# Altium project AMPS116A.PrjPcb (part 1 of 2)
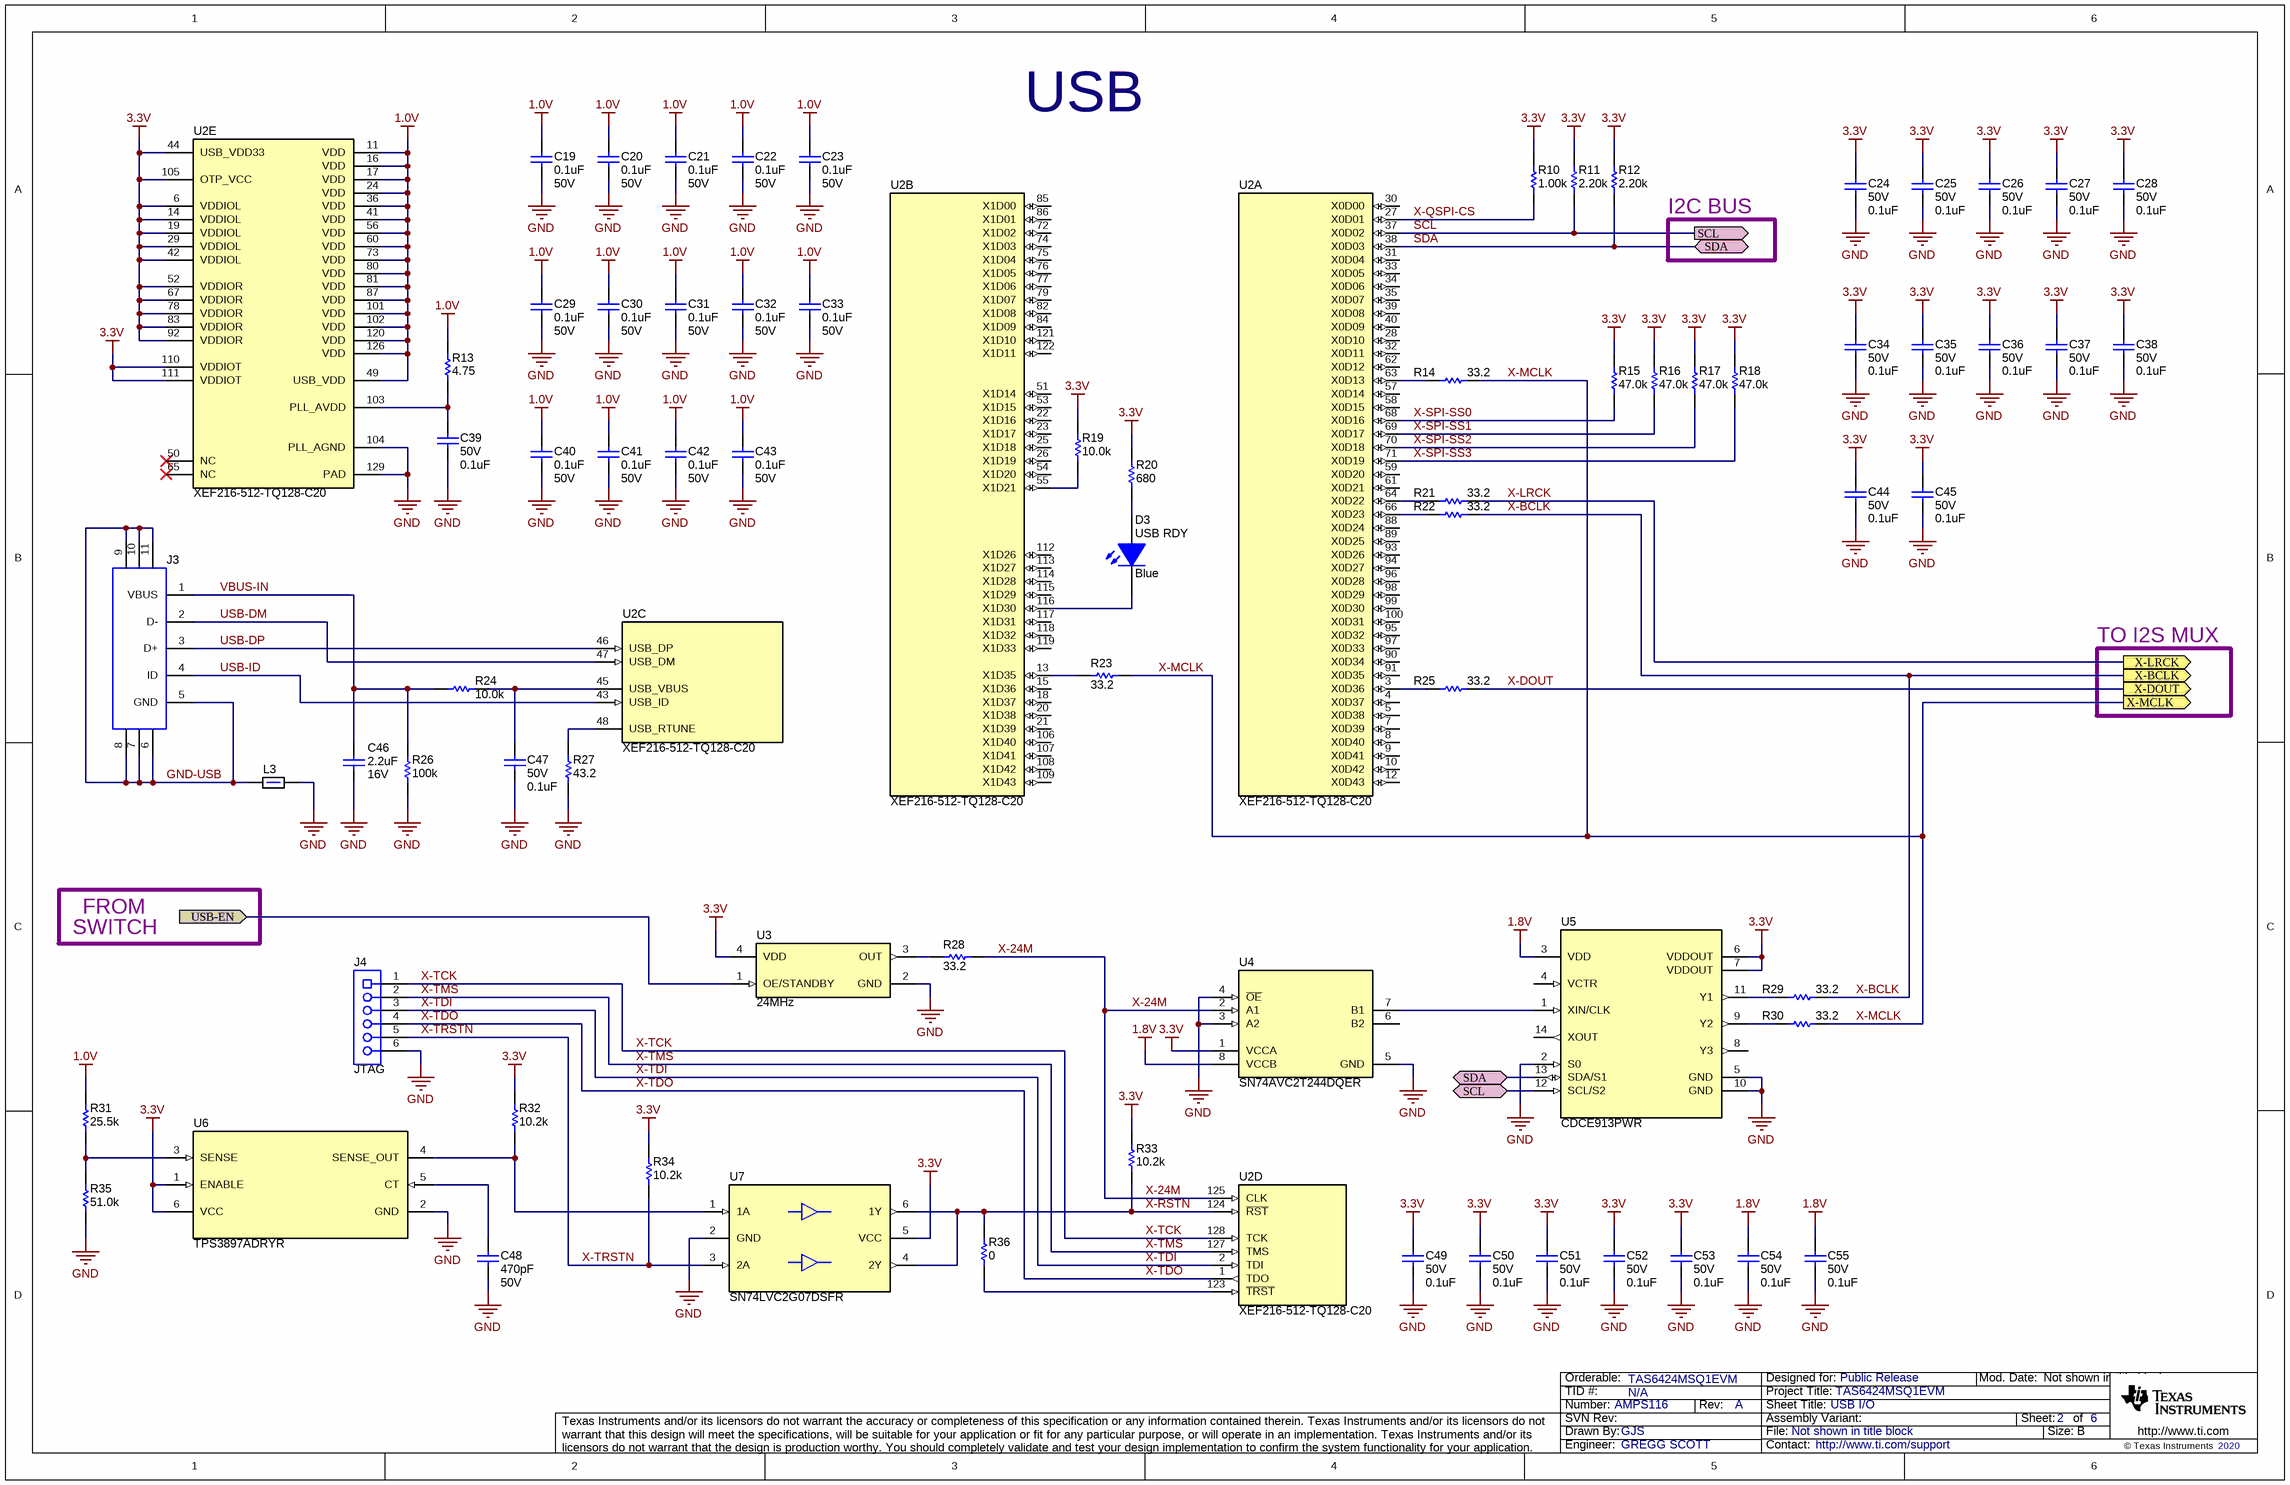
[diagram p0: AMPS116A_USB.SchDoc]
TID: N/A; TechSupport: http://www.ti.com/support; SCH_Rev: A; PRJ_Title: TAS6424MSQ1EVM; PRJ_Number: AMPS116; PRJ_Engineer: GREGG SCOTT; PRJ_Customer: Public Release; PCB_Rev: A; PCB_Layout: GJS; EVM_Orderable: TAS6424MSQ1EVM; CopyrightYear: 2020
5 sheets, 258 parts. Net scope: flat (ports and power ports of the same name join across sheets).
Board file: AMPS116A_EVM.PcbDoc
Sheets:
  AMPS116A_USB.SchDoc
  AMPS116A_SPDIF.SchDoc
  AMPS116A_TAS6424-IO.SchDoc
  AMPS116A_PowerSupplies.SchDoc
  AMPS116A_EVM_Hardware.SchDoc

## Sheet AMPS116A_USB.SchDoc: USB I/O
size 431 x 279 mm; Date: Not shown in title block; ApprovedBy: Not shown in title block; CheckedBy: Not shown in title block; Author: Not shown in title block; CompanyName: Not shown in title block; DrawnBy: GJS; Engineer: Not shown in title block; Organization: Not shown in title block; Address1: Not shown in title block; Address2: Not shown in title block; Address3: Not shown in title block; Address4: Not shown in title block; DocumentNumber: 2; Revision: Use project parameter SCH_Rev; SheetNumber: 2; SheetTotal: 6; PageSetup: Record=PageOptions¦CenterHorizontal=True¦CenterVertical=True¦PrintScale=0.77¦XCorrection=1.00¦YCorrection=1.00¦PrintKind=0¦BorderSize=5000000¦LeftOffset=0¦BottomOffset=0¦Orientation=2¦PaperLength=1000¦PaperWidth=1000¦Scale=100¦PaperSource=15¦PrintQuality=600¦MediaType=1¦DitherType=10¦PrintScaleMode=1¦PaperKind=Tabloid (11 x 17")¦PaperIndex=17

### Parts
C19  ValueDisplayed: 0.1uF  VDC_V: 50V  [0402L]  (hidden comment: Capacitor)
C20  ValueDisplayed: 0.1uF  VDC_V: 50V  [0402L]  (hidden comment: Capacitor)
C21  ValueDisplayed: 0.1uF  VDC_V: 50V  [0402L]  (hidden comment: Capacitor)
C22  ValueDisplayed: 0.1uF  VDC_V: 50V  [0402L]  (hidden comment: Capacitor)
C23  ValueDisplayed: 0.1uF  VDC_V: 50V  [0402L]  (hidden comment: Capacitor)
C24  VDC_V: 50V  ValueDisplayed: 0.1uF  [0402L]  (hidden comment: C1005X7R1H104K050BB)
C25  VDC_V: 50V  ValueDisplayed: 0.1uF  [0402L]  (hidden comment: C1005X7R1H104K050BB)
C26  VDC_V: 50V  ValueDisplayed: 0.1uF  [0402L]  (hidden comment: C1005X7R1H104K050BB)
C27  VDC_V: 50V  ValueDisplayed: 0.1uF  [0402L]  (hidden comment: C1005X7R1H104K050BB)
C28  VDC_V: 50V  ValueDisplayed: 0.1uF  [0402L]  (hidden comment: C1005X7R1H104K050BB)
C29  ValueDisplayed: 0.1uF  VDC_V: 50V  [0402L]  (hidden comment: Capacitor)
C30  ValueDisplayed: 0.1uF  VDC_V: 50V  [0402L]  (hidden comment: Capacitor)
C31  ValueDisplayed: 0.1uF  VDC_V: 50V  [0402L]  (hidden comment: Capacitor)
C32  ValueDisplayed: 0.1uF  VDC_V: 50V  [0402L]  (hidden comment: Capacitor)
C33  ValueDisplayed: 0.1uF  VDC_V: 50V  [0402L]  (hidden comment: Capacitor)
C34  VDC_V: 50V  ValueDisplayed: 0.1uF  [0402L]  (hidden comment: C1005X7R1H104K050BB)
C35  VDC_V: 50V  ValueDisplayed: 0.1uF  [0402L]  (hidden comment: C1005X7R1H104K050BB)
C36  VDC_V: 50V  ValueDisplayed: 0.1uF  [0402L]  (hidden comment: C1005X7R1H104K050BB)
C37  VDC_V: 50V  ValueDisplayed: 0.1uF  [0402L]  (hidden comment: C1005X7R1H104K050BB)
C38  VDC_V: 50V  ValueDisplayed: 0.1uF  [0402L]  (hidden comment: C1005X7R1H104K050BB)
C39  VDC_V: 50V  ValueDisplayed: 0.1uF  [0402L]  (hidden comment: C1005X7R1H104K050BB)
C40  ValueDisplayed: 0.1uF  VDC_V: 50V  [0402L]  (hidden comment: Capacitor)
C41  ValueDisplayed: 0.1uF  VDC_V: 50V  [0402L]  (hidden comment: Capacitor)
C42  ValueDisplayed: 0.1uF  VDC_V: 50V  [0402L]  (hidden comment: Capacitor)
C43  ValueDisplayed: 0.1uF  VDC_V: 50V  [0402L]  (hidden comment: Capacitor)
C44  VDC_V: 50V  ValueDisplayed: 0.1uF  [0402L]  (hidden comment: C1005X7R1H104K050BB)
C45  VDC_V: 50V  ValueDisplayed: 0.1uF  [0402L]  (hidden comment: C1005X7R1H104K050BB)
C46  VDC_V: 16V  ValueDisplayed: 2.2uF  [0603L]  (hidden comment: EMK107BB7225MA-T)
C47  VDC_V: 50V  ValueDisplayed: 0.1uF  [0402L]  (hidden comment: C1005X7R1H104K050BB)
C48  Cap_F: 470pF  VDC_V: 50V  [0402L]  (hidden comment: GRT1555C1H471JA02D)
C49  VDC_V: 50V  ValueDisplayed: 0.1uF  [0402L]  (hidden comment: C1005X7R1H104K050BB)
C50  VDC_V: 50V  ValueDisplayed: 0.1uF  [0402L]  (hidden comment: C1005X7R1H104K050BB)
C51  VDC_V: 50V  ValueDisplayed: 0.1uF  [0402L]  (hidden comment: C1005X7R1H104K050BB)
C52  VDC_V: 50V  ValueDisplayed: 0.1uF  [0402L]  (hidden comment: C1005X7R1H104K050BB)
C53  VDC_V: 50V  ValueDisplayed: 0.1uF  [0402L]  (hidden comment: C1005X7R1H104K050BB)
C54  VDC_V: 50V  ValueDisplayed: 0.1uF  [0402L]  (hidden comment: C1005X7R1H104K050BB)
C55  VDC_V: 50V  ValueDisplayed: 0.1uF  [0402L]  (hidden comment: C1005X7R1H104K050BB)
D3  USB RDY  value Blue  [LTST-C170TBKT_Blue]
J3  475890001  [Molex_0475890001]  (value not drawn)
J4  JTAG  [SULLINS_LPPB061NGCN-RC]
L3  MPZ2012S300AT000  [MPZ2012]  (value not drawn)
R10  ValueDisplayed: 1.00k  [0402L]  (hidden comment: ERJ-2RKF1001X)
R11  ValueDisplayed: 2.20k  [0402L]  (hidden comment: ERJ-2RKF2201X)
R12  ValueDisplayed: 2.20k  [0402L]  (hidden comment: ERJ-2RKF2201X)
R13  ValueDisplayed: 4.75  [0603L]  (hidden comment: RC0603FR-074R75L)
R14  ValueDisplayed: 33.2  [0201L]  (hidden comment: Resistor)
R15  ValueDisplayed: 47.0k  [0402L]  (hidden comment: RC0402FR-0747KL)
R16  ValueDisplayed: 47.0k  [0402L]  (hidden comment: RC0402FR-0747KL)
R17  ValueDisplayed: 47.0k  [0402L]  (hidden comment: RC0402FR-0747KL)
R18  ValueDisplayed: 47.0k  [0402L]  (hidden comment: RC0402FR-0747KL)
R19  ValueDisplayed: 10.0k  [0402L]  (hidden comment: RC0402FR-0710KL)
R20  ValueDisplayed: 680  [0603L]  (hidden comment: RC0603FR-07680RL)
R21  ValueDisplayed: 33.2  [0201L]  (hidden comment: Resistor)
R22  ValueDisplayed: 33.2  [0201L]  (hidden comment: Resistor)
R23  ValueDisplayed: 33.2  [0201L]  (hidden comment: Resistor)
R24  ValueDisplayed: 10.0k  [0402L]  (hidden comment: RC0402FR-0710KL)
R25  ValueDisplayed: 33.2  [0201L]  (hidden comment: Resistor)
R26  ValueDisplayed: 100k  [0402L]  (hidden comment: ERJ-2RKF1003X)
R27  ValueDisplayed: 43.2  [0603L]  (hidden comment: RC0603FR-0743R2L)
R28  ValueDisplayed: 33.2  [0201L]  (hidden comment: Resistor)
R29  ValueDisplayed: 33.2  [0201L]  (hidden comment: Resistor)
R30  ValueDisplayed: 33.2  [0201L]  (hidden comment: Resistor)
R31  ValueDisplayed: 25.5k  [0201L]  (hidden comment: Resistor)
R32  ValueDisplayed: 10.2k  [0201L]  (hidden comment: RC0201FR-0710K2L)
R33  ValueDisplayed: 10.2k  [0201L]  (hidden comment: RC0201FR-0710K2L)
R34  ValueDisplayed: 10.2k  [0201L]  (hidden comment: RC0201FR-0710K2L)
R35  ValueDisplayed: 51.0k  [0201L]  (hidden comment: Resistor)
R36  ValueDisplayed: 0  [0402L]  (hidden comment: ERJ-2GE0R00X)
U2  XEF216-512-TQ128-C20  [TQFP-128]  (parts A,B,C,D,E of 5)
U3  Frequency_Fixed: 24MHz  [Abracon_ASTMLPA]  (hidden comment: OSC_4P_1_OE-STBY)
U4  SN74AVC2T244DQER  [DQE0008A]
U5  CDCE913PWR  [PW0014A_L]
U6  TPS3897ADRYR  [DRY0006A]
U7  SN74LVC2G07DSFR  [DSF0006A]

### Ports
SCL (bidir), SCL (out), SDA (bidir), USB-EN (in), X-BCLK (out), X-DOUT (out), X-LRCK (out), X-MCLK (out)

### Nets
1.0V: C19.2 C20.2 C21.2 C22.2 C23.2 C29.2 C30.2 C31.2 C32.2 C33.2 C40.2 C41.2 C42.2 C43.2 R13.1 R31.1 U2.11(VDD) U2.16(VDD) U2.17(VDD) U2.24(VDD) U2.36(VDD) U2.41(VDD) U2.49(USB_VDD) U2.56(VDD) U2.60(VDD) U2.73(VDD) U2.80(VDD) U2.81(VDD) U2.87(VDD) U2.101(VDD) U2.102(VDD) U2.120(VDD) U2.126(VDD)
1.8V: C54.1 C55.1 U4.8(VCCB) U5.3(VDD)
3.3V: C24.1 C25.1 C26.1 C27.1 C28.1 C34.1 C35.1 C36.1 C37.1 C38.1 C44.1 C45.1 C49.1 C50.1 C51.1 C52.1 C53.1 R10.1 R11.1 R12.1 R15.2 R16.2 R17.2 R18.2 R19.2 R20.1 R32.1 R33.1 R34.1 U2.6(VDDIOL) U2.14(VDDIOL) U2.19(VDDIOL) U2.29(VDDIOL) U2.42(VDDIOL) U2.44(USB_VDD33) U2.52(VDDIOR) U2.67(VDDIOR) U2.78(VDDIOR) U2.83(VDDIOR) U2.92(VDDIOR) U2.105(OTP_VCC) U2.110(VDDIOT) U2.111(VDDIOT) U3.4(VDD) U4.1(VCCA) U5.6(VDDOUT) U5.7(VDDOUT) U6.1(ENABLE) U6.6(VCC) U7.5(VCC)
GND: C19.1 C20.1 C21.1 C22.1 C23.1 C24.2 C25.2 C26.2 C27.2 C28.2 C29.1 C30.1 C31.1 C32.1 C33.1 C34.2 C35.2 C36.2 C37.2 C38.2 C39.2 C40.1 C41.1 C42.1 C43.1 C44.2 C45.2 C46.2 C47.2 C48.2 C49.2 C50.2 C51.2 C52.2 C53.2 C54.2 C55.2 J4.6 L3.2 R26.1 R27.1 R35.2 U2.104(PLL_AGND) U2.129(PAD) U3.2(GND) U4.3(A2) U4.4(~{OE}) U4.5(GND) U5.2(S0) U5.5(GND) U5.10(GND) U6.2(GND) U7.2(GND)
GND-USB: J3.5(GND) J3.6 J3.7 J3.8 J3.9 J3.10 J3.11 L3.1
SCL: R11.2 U2.37(X0D02) U5.12(SCL/S2) ; port SCL
SDA: R12.2 U2.38(X0D03) U5.13(SDA/S1) ; port SDA
USB-DM: J3.2(D-) U2.47(USB_DM)
USB-DP: J3.3(D+) U2.46(USB_DP)
USB-EN: U3.1(OE/STANDBY) ; port USB-EN
USB-ID: J3.4(ID) U2.43(USB_ID)
VBUS-IN: C46.1 J3.1(VBUS) R24.2 R26.2
X-24M: R28.2 U2.125(CLK) U4.2(A1)
X-BCLK: R22.2 R29.2 ; port X-BCLK
X-DOUT: R25.2 ; port X-DOUT
X-LRCK: R21.2 ; port X-LRCK
X-MCLK: R14.2 R23.2 R30.2 ; port X-MCLK
X-QSPI-CS: R10.2 U2.27(X0D01)
X-RSTN: R33.2 R36.2 U2.124(~{RST}) U7.4(2Y) U7.6(1Y)
X-SPI-SS0: R15.1 U2.68(X0D16)
X-SPI-SS1: R16.1 U2.69(X0D17)
X-SPI-SS2: R17.1 U2.70(X0D18)
X-SPI-SS3: R18.1 U2.71(X0D19)
X-TCK: J4.1 U2.128(TCK)
X-TDI: J4.3 U2.2(TDI)
X-TDO: J4.4 U2.1(TDO)
X-TMS: J4.2 U2.127(TMS)
X-TRSTN: J4.5 R34.2 U7.3(2A)
NetC39_1: C39.1 R13.2 U2.103(PLL_AVDD)
NetC47_1: C47.1 R24.1 U2.45(USB_VBUS)
NetC48_1: C48.1 U6.5(CT)
NetD3_1: D3.1(A) R20.2
NetD3_2: D3.2(K) U2.116(X1D30)
NetR14_1: R14.1 U2.63(X0D13)
NetR19_1: R19.1 U2.55(X1D21)
NetR21_1: R21.1 U2.64(X0D22)
NetR22_1: R22.1 U2.66(X0D23)
NetR23_1: R23.1 U2.13(X1D35)
NetR25_1: R25.1 U2.3(X0D36)
NetR27_2: R27.2 U2.48(USB_RTUNE)
NetR28_1: R28.1 U3.3(OUT)
NetR29_1: R29.1 U5.11(Y1)
NetR30_1: R30.1 U5.9(Y2)
NetR31_2: R31.2 R35.1 U6.3(SENSE)
NetR32_2: R32.2 U6.4(SENSE_OUT) U7.1(1A)
NetR36_1: R36.1 U2.123(~{TRST})
NetU4_7: U4.7(B1) U5.1(XIN/CLK)

Not connected (* = marked no-connect by the designer): U2 4(X0D37) 5(X0D38) 7(X0D39) 8(X0D40) 9(X0D41) 10(X0D42) 12(X0D43) 15(X1D36) 18(X1D37) 20(X1D38) 21(X1D39) 22(X1D16) 23(X1D17) 25(X1D18) 26(X1D19) 28(X0D10) 30(X0D00) 31(X0D04) 32(X0D11) 33(X0D05) 34(X0D06) 35(X0D07) 39(X0D08) 40(X0D09) 50(NC)* 51(X1D14) 53(X1D15) 54(X1D20) 57(X0D14) 58(X0D15) 59(X0D20) 61(X0D21) 62(X0D12) 65(NC)* 72(X1D02) 74(X1D03) 75(X1D04) 76(X1D05) 77(X1D06) 79(X1D07) 82(X1D08) 84(X1D09) 85(X1D00) 86(X1D01) 88(X0D24) 89(X0D25) 90(X0D34) 91(X0D35) 93(X0D26) 94(X0D27) 95(X0D32) 96(X0D28) 97(X0D33) 98(X0D29) 99(X0D30) 100(X0D31) 106(X1D40) 107(X1D41) 108(X1D42) 109(X1D43) 112(X1D26) 113(X1D27) 114(X1D28) 115(X1D29) 117(X1D31) 118(X1D32) 119(X1D33) 121(X1D10) 122(X1D11); U4 6(B2); U5 4(VCTR) 8(Y3) 14(XOUT)

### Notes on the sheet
- USB
- I2C BUS
- TO I2S MUX
- SWITCH
- FROM

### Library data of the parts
C19-C23 C29-C33 C40-C43 = CMP-0006297-2: CAP, CERM, 0.1 uF, 50 V, +/- 10%, X7R, 0402; PartNumber: C1005X7R1H104K050BB; Manufacturer: TDK; Polarized: N; Value: 0.1uF; U/M: EA; Cap_F: 100nF; ESR_ohm: 0.039064; Value1: 0.039064 ohm; IRMS_A: 8.14669dA; TaMin_C: -55°C; TaMax_C: 125°C; Cap_Case: 0402; SizeArea_mm2: 0.5; SizeAreaWB_mm2: 3; SizeX_mm: 1; SizeZ_mm: 0.6; AEC Category: Q200
C24-C28 C34-C39 C44 C45 C47 C49-C55 = CMP-0006297-2: CAP, CERM, 0.1 uF, 50 V, +/- 10%, X7R, 0402; Manufacturer: TDK; TaMin_C: -55°C; Polarized: N; SizeAreaWB_mm2: 3; Value1: 0.039064 ohm; U/M: EA; Value: 0.1uF; TaMax_C: 125°C; SizeZ_mm: 0.6; SizeX_mm: 1; SizeY_mm: 0.5; Cap_Case: 0402; Cap_F: 100nF; AEC Category: Q200; ESR_ohm: 0.039064; IRMS_A: 8.14669dA
C46 = CMP-0064934-4: CAP, CERM, 2.2 uF, 16 V,+/- 10%, X7R, 0603; Manufacturer: Taiyo Yuden; TaMin_C: -55°C; Polarized: N; SizeAreaWB_mm2: 4.68; Value1: Unknown; U/M: EA; Value: 2.2uF; TaMax_C: 125°C; SizeZ_mm: 1; SizeX_mm: 1.6; SizeY_mm: 0.8; Cap_Case: 0603; SizeArea_mm2: 1.28; CompType: Capacitor; Cap_F: 2.2µF; AEC Category: Q200
C48 = CMP-0860800-1: CAP, CERM, 470 pF, 50 V,+/- 5%, C0G, AEC-Q200 Grade 1, 0402; Manufacturer: MuRata; U/M: EA; Polarized: N; AEC Category: Q200; SizeY_mm: 0.5; SizeAreaWB_mm2: 3; AEC Qualified: Y; TaMax_C: 125°C; Value: 470pF; SizeX_mm: 1; TaMin_C: -55°C; Cap_Case: 0402; SizeZ_mm: 0.6
D3 = CMP-0002889-2: LED, Blue, SMD; PartNumber: LTST-C170TBKT; Manufacturer: Lite-On; Type: AlInGaP; Value1: W; Io_A: 20mA; Vf_V: 3.3V
J3 = CMP-0055301-1: Connector, Receptacle, Micro-USB Type AB, R/A, Bottom Mount SMT; Manufacturer: Molex; CNHeader: FALSE; Green_Lifecycle: Active; Gender: Female; Green_REACh: Passed; CompType: USB; CT: TRUE
J4 = CMP-0054640-1: Receptacle, 50mil, 6x1, Gold, R/A, TH; PartNumber: LPPB061NGCN-RC; Manufacturer: Sullins Connector Solutions; CompType: Socket Strip; Pitch_mm: 1.27; Gender: Female; Row_Count: 1; CNHeader: FALSE; CT: TRUE; Green_Lifecycle: Active; Green_REACh: Passed
L3 = CMP-0003428-2: Ferrite Bead, 30 ohm @ 100 MHz, 6 A, 0805; Manufacturer: TDK; ZTyp@100MHz_Ohm: 30; SizeAreaWB_mm2: 6.75; DCR_ohm: 0.01; Value1: 0.01 ohm; Value: 30 ohm; Imax_A: 6A; SizeZ_mm: 1.45; SizeX_mm: 2; SizeY_mm: 1.25; SizeArea_mm2: 2.5
R10 = CMP-0026657-1: RES, 1.00 k, 1%, 0.1 W, 0402; Manufacturer: Panasonic; Power_W: 100mW; TempCo: 100 ppm/C; Value_Code: 1k00; U/M: EA; Value: 1.00k; EIA_Code: E96; Res_ohm: 1k; SizeX_mm: 1; SizeY_mm: 0.5; SizeZ_mm: 0.6; Value2: 0.1W; CompType: Resistor; VDC_V: 50V; AEC Category: Q200
R11 R12 = CMP-0026681-1: RES, 2.20 k, 1%, 0.1 W, 0402; Manufacturer: Panasonic; Value: 2.20k; Res_ohm: 2.2k; Value_Code: 2k20; Power_W: 100mW; Value2: 0.1W; VDC_V: 50V; TempCo: 100 ppm/C; AEC Category: Q200; SizeArea_mm2: 0.5; SizeX_mm: 1; SizeZ_mm: 0.6; U/M: EA
R13 = CMP-0023160-5: RES, 4.75, 1%, 0.1 W, 0603; Manufacturer: Yageo; Power_W: 100mW; TempCo: 200 ppm/C; Value_Code: 4R75; Value: 4.75; EIA_Code: E96; SizeX_mm: 1.6; SizeY_mm: 0.8; SizeZ_mm: 1; Value2: 0.1W; SizeArea_mm2: 1.28; CompType: Resistor; AEC Qualified: N; VDC_V: 75V; AEC Category: Q200; SizeAreaWB_mm2: 4.68
R14 R21-R23 R25 R29 R30 = CMP-0027614-1: RES, 33.2, 1%, 0.05 W, 0201; PartNumber: RC0201FR-0733R2L; Manufacturer: Yageo America; Value: 33.2; Value_Code: 33R2; Power_W: 50mW; Value2: 0.05W; VDC_V: 25V; TempCo: 200 ppm/C; SizeArea_mm2: 0.18; SizeX_mm: 0.6; SizeY_mm: 0.3; SizeZ_mm: 0.26; EIA_Code: E96; U/M: EA; AEC Category: Q200; AEC Qualified: N
R15-R18 = CMP-0026737-1: RES, 47.0 k, 1%, 0.0625 W, 0402; Manufacturer: Yageo America; Value: 47.0k; Res_ohm: 47k; Value_Code: 47k0; Power_W: 62.5mW; VDC_V: 50V; TempCo: 100 ppm/C; AEC Category: Q200; AEC Qualified: N; SizeArea_mm2: 0.5; SizeX_mm: 1; SizeZ_mm: 0.6; U/M: EA
R19 R24 = CMP-0078669-1: RES, 10.0 k, 1%, 0.063 W, 0402; Manufacturer: Yageo America; Power_W: 63mW; Green_Lifecycle: Active; TempCo: 100 ppm/C; Value_Code: 10k0; Green_REACh: Passed; Value: 10.0k; EIA_Code: E96; Res_ohm: 10k; SizeX_mm: 1; SizeY_mm: 0.5; SizeZ_mm: 0.6; Value2: 0.063W; CompType: Resistor; AEC Qualified: N; AEC Category: Q200
R20 = CMP-0023235-5: RES, 680, 1%, 0.1 W, 0603; Manufacturer: Yageo; Power_W: 100mW; TempCo: 100 ppm/C; Value_Code: 680R; Value: 680; SizeX_mm: 1.6; SizeY_mm: 0.8; SizeZ_mm: 1; Value2: 0.1W; SizeArea_mm2: 1.28; CompType: Resistor; AEC Qualified: N; VDC_V: 75V; AEC Category: Q200; SizeAreaWB_mm2: 4.68
R26 = CMP-0026659-2: RES, 100 k, 1%, 0.1 W, 0402; Manufacturer: Panasonic; Value: 100k; Power_W: 100mW; Value2: 0.1W; VDC_V: 50V; TempCo: 100 ppm/C; EIA_Code: E96; U/M: EA; AEC Category: Q200; AEC Qualified: Yes; AEC Grade: 0; SizeArea_mm2: 0.5; SizeX_mm: 1; SizeZ_mm: 0.6
R27 = CMP-0023114-5: RES, 43.2, 1%, 0.1 W, 0603; Manufacturer: Yageo; Power_W: 100mW; TempCo: 100 ppm/C; Value_Code: 43R2; Value: 43.2; EIA_Code: E96; SizeX_mm: 1.6; SizeY_mm: 0.8; SizeZ_mm: 1; Value2: 0.1W; SizeArea_mm2: 1.28; CompType: Resistor; AEC Qualified: N; VDC_V: 75V; AEC Category: Q200; SizeAreaWB_mm2: 4.68
R28 = CMP-0027614-1: RES, 33.2, 1%, 0.05 W, 0201; PartNumber: RC0201FR-0733R2L; Manufacturer: Yageo America; Value: 33.2; Value_Code: 33R2; Power_W: 50mW; Value2: 0.05W; VDC_V: 25V; TempCo: 200 ppm/C; EIA_Code: E96; U/M: EA; SizeArea_mm2: 0.18; SizeX_mm: 0.6; SizeY_mm: 0.3; SizeZ_mm: 0.26; AEC Category: Q200; AEC Qualified: N
R31 = CMP-0027523-1: RES, 25.5 k, 1%, 0.05 W, 0201; PartNumber: RC0201FR-0725K5L; Manufacturer: Yageo America; Value: 25.5k; Value_Code: 25k5; Power_W: 50mW; Value2: 0.05W; VDC_V: 25V; TempCo: 200 ppm/C; SizeArea_mm2: 0.18; SizeX_mm: 0.6; SizeY_mm: 0.3; SizeZ_mm: 0.26; EIA_Code: E96; U/M: EA; AEC Category: Q200; AEC Qualified: N
R32-R34 = CMP-0027301-2: RES, 10.2 k, 1%, 0.05 W, 0201; Manufacturer: Yageo America; Value: 10.2k; Value_Code: 10k2; Power_W: 50mW; Value2: 0.05W; VDC_V: 25V; TempCo: 200 ppm/C; SizeArea_mm2: 0.18; SizeX_mm: 0.6; SizeY_mm: 0.3; SizeZ_mm: 0.26; EIA_Code: E96; AEC Category: Q200; AEC Qualified: N; U/M: EA
R35 = CMP-0027757-1: RES, 51.0 k, 1%, 0.05 W, 0201; PartNumber: RC0201FR-0751KL; Manufacturer: Yageo America; Value: 51.0k; Res_ohm: 51k; Value_Code: 51k0; Power_W: 50mW; Value2: 0.05W; VDC_V: 25V; TempCo: 200 ppm/C; SizeArea_mm2: 0.18; SizeX_mm: 0.6; SizeY_mm: 0.3; SizeZ_mm: 0.26; U/M: EA; AEC Category: Q200; AEC Qualified: N
R36 = CMP-0026992-3: RES, 0, 5%, 0.1 W, AEC-Q200 Grade 0, 0402; Manufacturer: Panasonic; Power_W: 100mW; TempCo: 600 ppm/C; Value_Code: 0000; Value: 0; EIA_Code: E24; SizeX_mm: 1; SizeY_mm: 0.5; SizeZ_mm: 0.6; Value2: 0.1W; CompType: Resistor; AEC Qualified: Y; VDC_V: 50V; AEC Category: Q200; SizeAreaWB_mm2: 3
U2 = CMP-0004936-1: IC MCU 512KB RAM, 128TQFP; Manufacturer: XMOS semiconductor
U3 = CMP-0006105-3: OSC, 24 MHz, 2.25 - 3.63 V, SMD; PartNumber: ASTMLPA-24.000MHZ-EJ-E-T; Manufacturer: Abracon Corporation; CompType: Oscillator; TaMin_C: -20°C; TaMax_C: 70°C; Frequency Stability: +/-20ppm
U4 = CMP-0050935-3: Dual-Bit Dual-Supply Bus Transceiver, DQE0008A, LARGE T&R; Manufacturer: Texas Instruments; tpd @ Nom Voltage(Max)(ns): 20,7,3.5; Schmitt Trigger: No; Bits(#): 2; F @ Nom Voltage(Max)(Mhz): 100; Technology Family: AVC; VCC(Min)(V): 0.9; Sub-Family: Dual Supply Translator; Voltage(Nom)(V): 0.9,1.2,1.5,1.8,2.5,3.3; VCC(Max)(V): 3.6; ICC @ Nom Voltage(Max)(mA): 0.0009; AEC Category: Q200; Output Drive (IOL/IOH)(Max)(mA): 24/-24; Output Type: CMOS; Rating: Catalog; Logic: True; CompType: IC
U5 = CMP-0065668-3: Programmable 1-PLL VCXO Clock Synthesizer with 2.5-V or 3.3-V LVCMOS Outputs, PW0014A (TSSOP-14); Alternate Manufacturer: Texas Instruments; AEC Category: Q200; SizeArea_mm2: 32.0; AEC Qualified: N; CompType: IC; Rating: Catalog; SizeY_mm: 5.0; SizeX_mm: 6.4; SizeZ_mm: 1.2; SizeAreaWB_mm2: 58.8
U6 = CMP-0032427-3: Single-Channel Ultra-Small Adjustable Supervisory Circuit With Active-High Open-Drain Output, DRY0006A (USON-6); Manufacturer: Texas Instruments; Iq(Typ)(uA): 6; Time Delay(ms): 0.04, Programmable; VCC(Min)(V): 1.7; Reset Threshold Accuracy(%): 0.25; Enable Pin: TRUE; Output Driver Type / Reset Output: Active-High, Open-drain; # of Supplies Monitored: 1; Rating: Catalog; VCC(Max)(V): 6.5; AEC Category: Q200; AEC Qualified: N; CompType: IC; SizeAreaWB_mm2: 4.9; SizeArea_mm2: 1.45; SizeX_mm: 1.0; SizeZ_mm: 0.6
U7 = CMP-0051795-5: Enhanced Product Dual Buffer/Driver with Open-Drain Output, DCK0006A (SOT-SC70-6); Manufacturer: Texas Instruments; Output Type: CMOS; Bits(#): 2; Input Type: CMOS/TTL; Technology Family: LVC; Schmitt Trigger: No; VCC(Max)(V): 5.5; Sub-Family: Inverting Buffer/Driver; Rating: Catalog; Output Drive (IOL/IOH)(Max)(mA): 32/-32; ICC @ Nom Voltage(Max)(mA): 0.01; VCC(Min)(V): 1.65; F @ Nom Voltage(Max)(Mhz): 150; Logic: True; Voltage(Nom)(V): 1.8,2.5,3.3,5; tpd @ Nom Voltage(Max)(ns): 8.6,4.4,3.7,2.9; AEC Category: Q200; AEC Qualified: N; CompType: IC; SizeAreaWB_mm2: 4; SizeArea_mm2: 1; SizeZ_mm: 0.4

## Sheet AMPS116A_SPDIF.SchDoc: SPDIF I/O
size 431 x 279 mm; Date: Not shown in title block; ApprovedBy: Not shown in title block; CheckedBy: Not shown in title block; Author: Not shown in title block; CompanyName: Not shown in title block; DrawnBy: GJS; Engineer: Not shown in title block; Organization: Not shown in title block; Address1: Not shown in title block; Address2: Not shown in title block; Address3: Not shown in title block; Address4: Not shown in title block; DocumentNumber: 3; SheetNumber: 3; SheetTotal: 6; PageSetup: Record=PageOptions¦CenterHorizontal=True¦CenterVertical=True¦PrintScale=0.98¦XCorrection=1.00¦YCorrection=1.00¦PrintKind=0¦BorderSize=5000000¦LeftOffset=0¦BottomOffset=0¦Orientation=2¦PaperLength=1000¦PaperWidth=1000¦Scale=100¦PaperSource=15¦PrintQuality=-3¦MediaType=1¦DitherType=10¦PrintScaleMode=1¦PaperKind=11 x 17¦PaperIndex=119
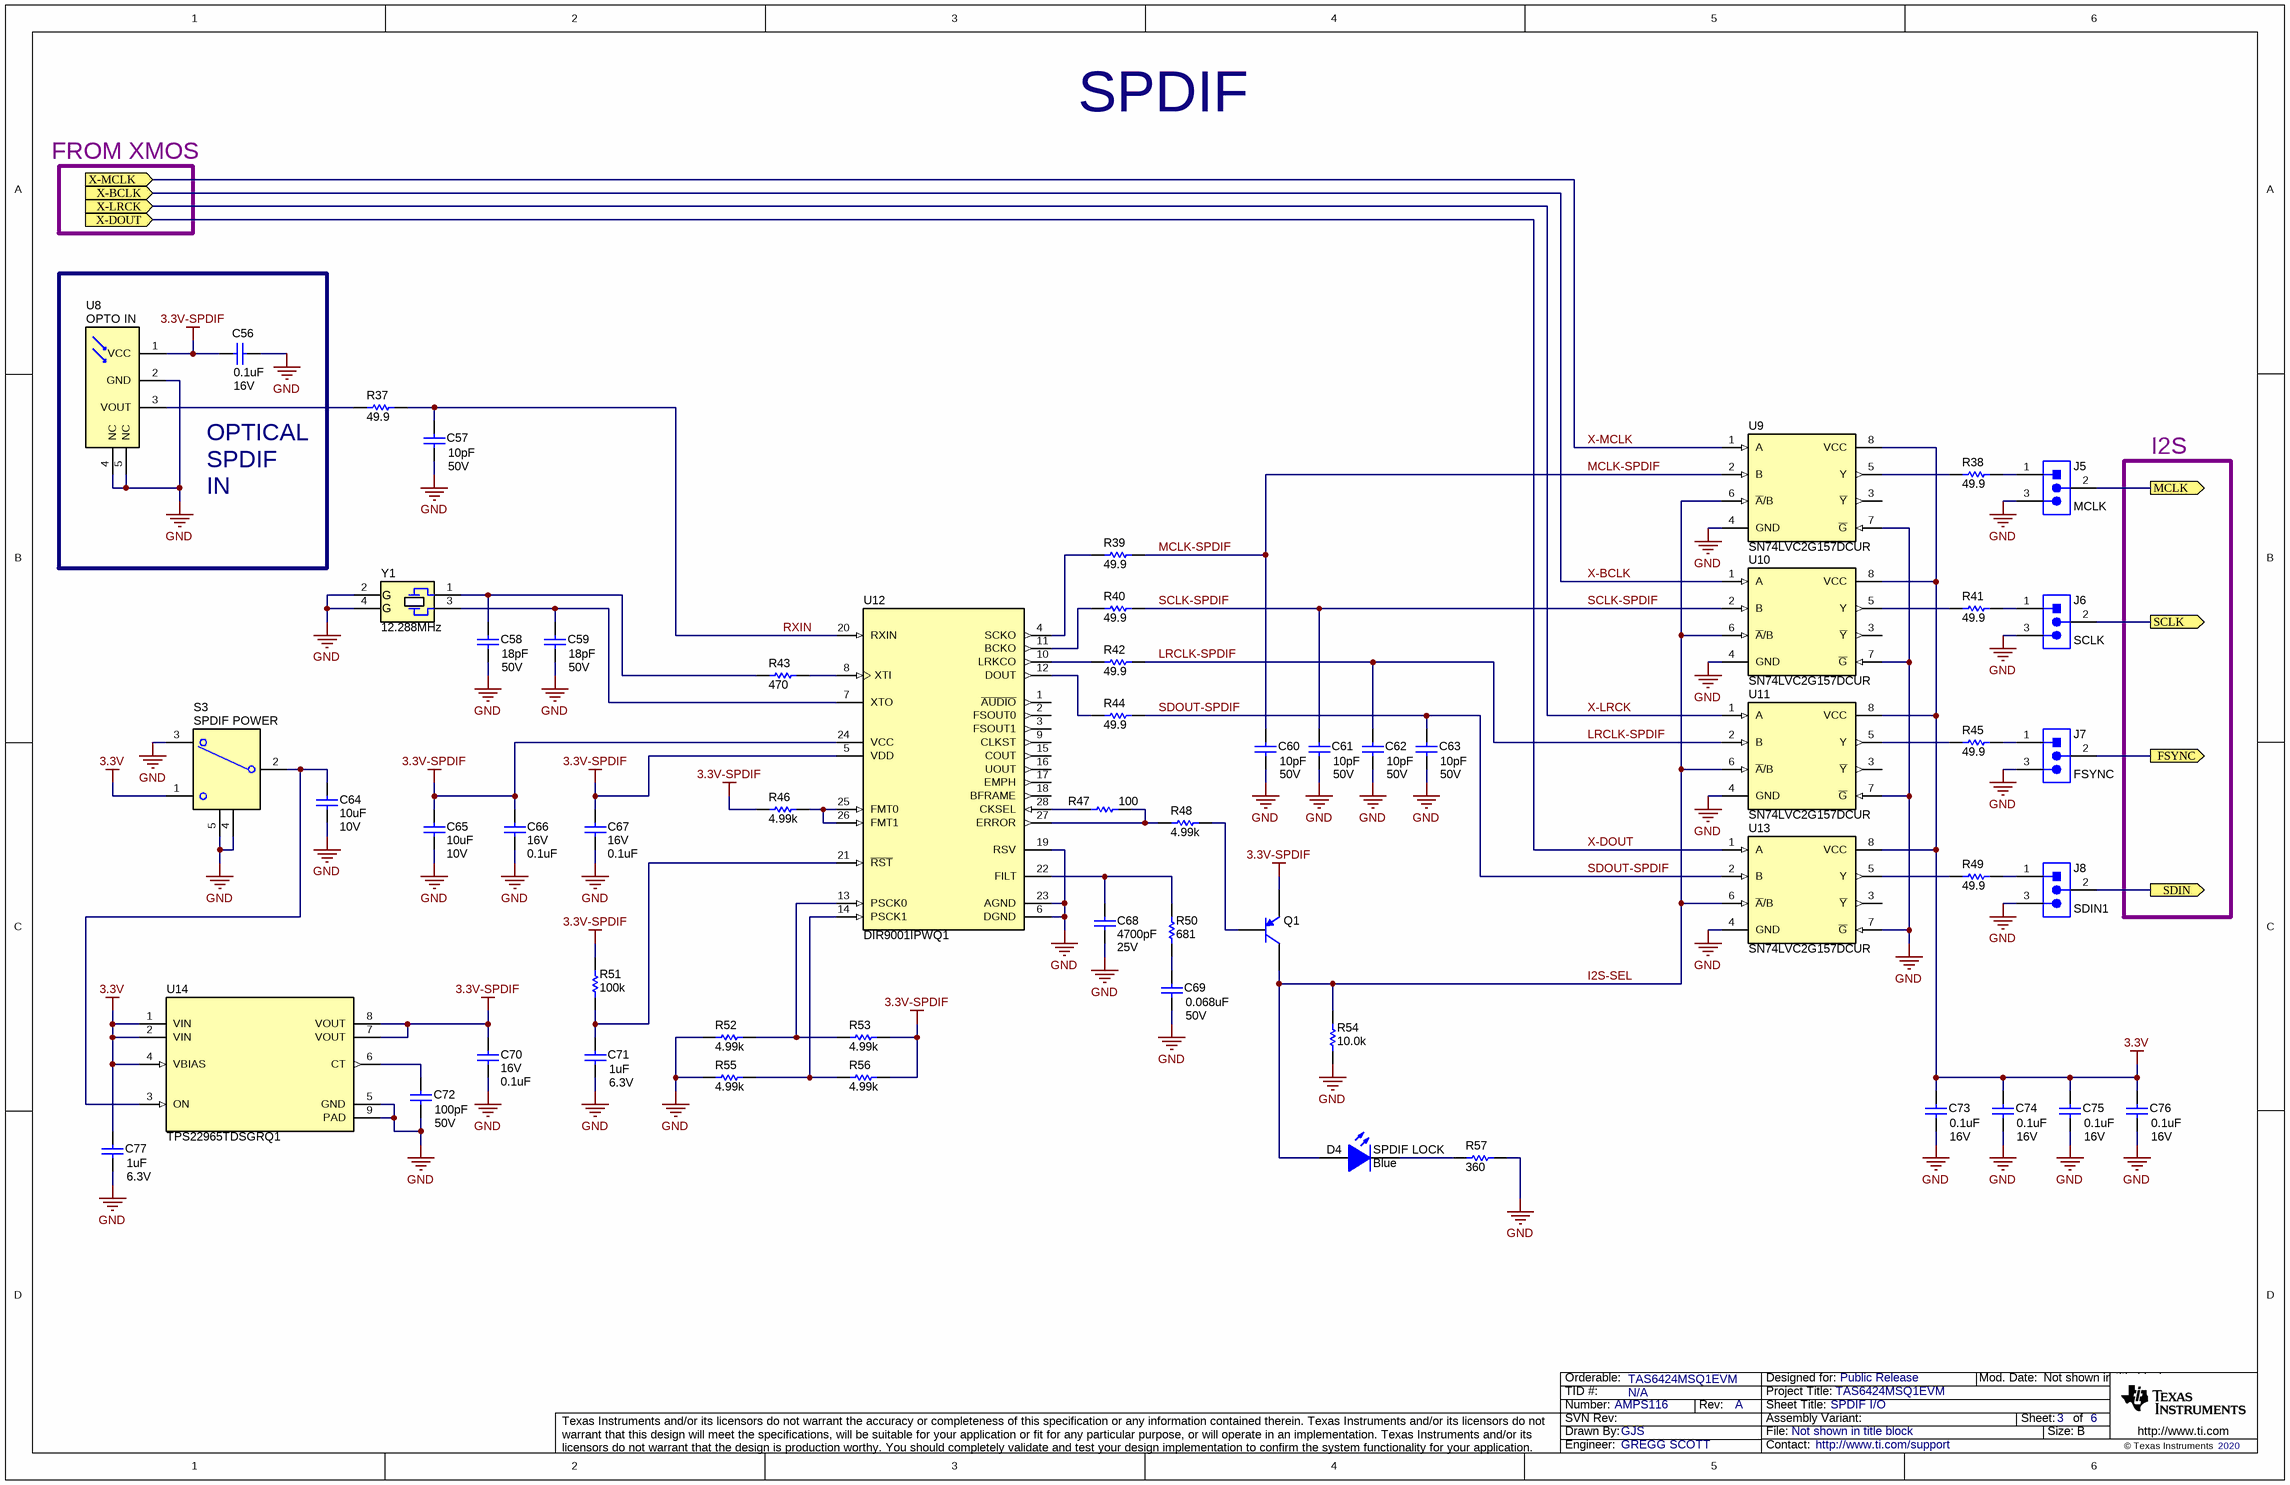
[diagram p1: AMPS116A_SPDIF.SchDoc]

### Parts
C56  VDC_V: 16V  ValueDisplayed: 0.1uF  [0402L]  (hidden comment: C0402C104K4RACAUTO)
C57  VDC_V: 50V  ValueDisplayed: 10pF  [0402L]  (hidden comment: 885012005055)
C58  VDC_V: 50V  ValueDisplayed: 18pF  [0603L]  (hidden comment: C0603C180J5GACTU)
C59  VDC_V: 50V  ValueDisplayed: 18pF  [0603L]  (hidden comment: C0603C180J5GACTU)
C60  VDC_V: 50V  ValueDisplayed: 10pF  [0402L]  (hidden comment: 885012005055)
C61  VDC_V: 50V  ValueDisplayed: 10pF  [0402L]  (hidden comment: 885012005055)
C62  VDC_V: 50V  ValueDisplayed: 10pF  [0402L]  (hidden comment: 885012005055)
C63  VDC_V: 50V  ValueDisplayed: 10pF  [0402L]  (hidden comment: 885012005055)
C64  ValueDisplayed: 10uF  VDC_V: 10V  [0603L]  (hidden comment: Capacitor)
C65  ValueDisplayed: 10uF  VDC_V: 10V  [0603L]  (hidden comment: Capacitor)
C66  VDC_V: 16V  ValueDisplayed: 0.1uF  [0402L]  (hidden comment: C0402C104K4RACAUTO)
C67  VDC_V: 16V  ValueDisplayed: 0.1uF  [0402L]  (hidden comment: C0402C104K4RACAUTO)
C68  ValueDisplayed: 4700pF  VDC_V: 25V  [0402L]  (hidden comment: CC0402KRX7R8BB472)
C69  VDC_V: 50V  ValueDisplayed: 0.068uF  [0402L]  (hidden comment: CGA2B3X7R1H683K050BB)
C70  VDC_V: 16V  ValueDisplayed: 0.1uF  [0402L]  (hidden comment: C0402C104K4RACAUTO)
C71  VDC_V: 6.3V  ValueDisplayed: 1uF  [0402L]  (hidden comment: GRM152R60J105ME15D)
C72  VDC_V: 50V  ValueDisplayed: 100pF  [0402L]  (hidden comment: CGA2B2C0G1H101J050BA)
C73  VDC_V: 16V  ValueDisplayed: 0.1uF  [0402L]  (hidden comment: C0402C104K4RACAUTO)
C74  VDC_V: 16V  ValueDisplayed: 0.1uF  [0402L]  (hidden comment: C0402C104K4RACAUTO)
C75  VDC_V: 16V  ValueDisplayed: 0.1uF  [0402L]  (hidden comment: C0402C104K4RACAUTO)
C76  VDC_V: 16V  ValueDisplayed: 0.1uF  [0402L]  (hidden comment: C0402C104K4RACAUTO)
C77  VDC_V: 6.3V  ValueDisplayed: 1uF  [0402L]  (hidden comment: GRM152R60J105ME15D)
D4  SPDIF LOCK  value Blue  [LTST-C170TBKT_Blue]
J5  MCLK  [PBC03SAAN]
J6  SCLK  [PBC03SAAN]
J7  FSYNC  [PBC03SAAN]
J8  SDIN1  [PBC03SAAN]
Q1  MMBT3906-7-F  [SOT-23]  (value not drawn)
R37  ValueDisplayed: 49.9  [0402L]  (hidden comment: Resistor)
R38  ValueDisplayed: 49.9  [0402L]  (hidden comment: Resistor)
R39  ValueDisplayed: 49.9  [0402L]  (hidden comment: Resistor)
R40  ValueDisplayed: 49.9  [0402L]  (hidden comment: Resistor)
R41  ValueDisplayed: 49.9  [0402L]  (hidden comment: Resistor)
R42  ValueDisplayed: 49.9  [0402L]  (hidden comment: Resistor)
R43  ValueDisplayed: 470  [0603L]  (hidden comment: Resistor)
R44  ValueDisplayed: 49.9  [0402L]  (hidden comment: Resistor)
R45  ValueDisplayed: 49.9  [0402L]  (hidden comment: Resistor)
R46  ValueDisplayed: 4.99k  [0402L]  (hidden comment: Resistor)
R47  ValueDisplayed: 100  [0402L]  (hidden comment: Resistor)
R48  ValueDisplayed: 4.99k  [0402L]  (hidden comment: Resistor)
R49  ValueDisplayed: 49.9  [0402L]  (hidden comment: Resistor)
R50  ValueDisplayed: 681  [0402L]  (hidden comment: Resistor)
R51  ValueDisplayed: 100k  [0402L]  (hidden comment: Resistor)
R52  ValueDisplayed: 4.99k  [0402L]  (hidden comment: DNP)
R53  ValueDisplayed: 4.99k  [0402L]  (hidden comment: Resistor)
R54  ValueDisplayed: 10.0k  [0402L]  (hidden comment: Resistor)
R55  ValueDisplayed: 4.99k  [0402L]  (hidden comment: Resistor)
R56  ValueDisplayed: 4.99k  [0402L]  (hidden comment: DNP)
R57  ValueDisplayed: 360  [0402L]  (hidden comment: Resistor)
S3  SPDIF POWER  [SW_FT1D-4M-Z]
U8  OPTO IN  [PLR135_T10]
U9  PartNumber: SN74LVC2G157DCUR  [DCU0008A_N]  (hidden comment: 74LVC2G157DCT)
U10  PartNumber: SN74LVC2G157DCUR  [DCU0008A_N]  (hidden comment: 74LVC2G157DCT)
U11  PartNumber: SN74LVC2G157DCUR  [DCU0008A_N]  (hidden comment: 74LVC2G157DCT)
U12  PartNumber: DIR9001IPWQ1  [PW0028A_N]  (hidden comment: TI-DIR9001-Q1-TSSOP_PW-28)
U13  PartNumber: SN74LVC2G157DCUR  [DCU0008A_N]  (hidden comment: 74LVC2G157DCT)
U14  PartNumber: TPS22965TDSGRQ1  [DSG0008B]  (hidden comment: TPS22965DSG)
Y1  Frequency_Fixed: 12.288MHz  [ABRACON_ABM8G]  (hidden comment: XTAL_4P_13_G24)

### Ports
FSYNC (out), MCLK (out), SCLK (out), SDIN (out), X-BCLK (in), X-DOUT (in), X-LRCK (in), X-MCLK (in)

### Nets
3.3V: C73.2 C74.2 C75.2 C76.2 C77.2 S3.1 U9.8(VCC) U10.8(VCC) U11.8(VCC) U13.8(VCC) U14.1(VIN) U14.2(VIN) U14.4(VBIAS)
3.3V-SPDIF: C56.1 C65.1 C66.2 C67.2 C70.1 Q1.2(E) R46.2 R51.2 R53.1 R56.1 U8.1(VCC) U12.5(VDD) U12.24(VCC) U14.7(VOUT) U14.8(VOUT)
GND: C56.2 C57.2 C58.2 C59.2 C60.2 C61.2 C62.2 C63.2 C64.2 C65.2 C66.1 C67.1 C68.2 C69.2 C70.2 C71.1 C72.2 C73.1 C74.1 C75.1 C76.1 C77.1 J5.3 J6.3 J7.3 J8.3 R52.2 R54.1 R55.2 R57.1 S3.3 S3.4 S3.5 U8.2(GND) U8.4(NC) U8.5(NC) U9.4(GND) U9.7(~{G}) U10.4(GND) U10.7(~{G}) U11.4(GND) U11.7(~{G}) U12.6(DGND) U12.19(RSV) U12.23(AGND) U13.4(GND) U13.7(~{G}) U14.5(GND) U14.9(PAD) Y1.2(GND) Y1.4(GND)
FSYNC: J7.2 ; port FSYNC
I2S-SEL: D4.1(A) Q1.3(C) R54.2 U9.6(~{A}/B) U10.6(~{A}/B) U11.6(~{A}/B) U13.6(~{A}/B)
LRCLK-SPDIF: C62.1 R42.2 U11.2(B)
MCLK: J5.2 ; port MCLK
MCLK-SPDIF: C60.1 R39.2 U9.2(B)
RXIN: C57.1 R37.2 U12.20(RXIN)
SCLK: J6.2 ; port SCLK
SCLK-SPDIF: C61.1 R40.2 U10.2(B)
SDIN: J8.2 ; port SDIN
SDOUT-SPDIF: C63.1 R44.2 U13.2(B)
X-BCLK: U10.1(A) ; port X-BCLK
X-DOUT: U13.1(A) ; port X-DOUT
X-LRCK: U11.1(A) ; port X-LRCK
X-MCLK: U9.1(A) ; port X-MCLK
NetC58_1: C58.1 R43.1 Y1.1
NetC59_1: C59.1 U12.7(XTO) Y1.3
NetC64_1: C64.1 S3.2(COM) U14.3(ON)
NetC68_1: C68.1 R50.2 U12.22(FILT)
NetC69_1: C69.1 R50.1
NetC71_2: C71.2 R51.1 U12.21(~{RST})
NetC72_1: C72.1 U14.6(CT)
NetD4_2: D4.2(K) R57.2
NetJ5_1: J5.1 R38.1
NetJ6_1: J6.1 R41.1
NetJ7_1: J7.1 R45.1
NetJ8_1: J8.1 R49.1
NetQ1_1: Q1.1(B) R48.1
NetR37_1: R37.1 U8.3(VOUT)
NetR38_2: R38.2 U9.5(Y)
NetR39_1: R39.1 U12.4(SCKO)
NetR40_1: R40.1 U12.11(BCKO)
NetR41_2: R41.2 U10.5(Y)
NetR42_1: R42.1 U12.10(LRKCO)
NetR43_2: R43.2 U12.8(XTI)
NetR44_1: R44.1 U12.12(DOUT)
NetR45_2: R45.2 U11.5(Y)
NetR46_1: R46.1 U12.25(FMT0) U12.26(FMT1)
NetR47_1: R47.1 U12.28(CKSEL)
NetR47_2: R47.2 R48.2 U12.27(ERROR)
NetR49_2: R49.2 U13.5(Y)
NetR52_1: R52.1 R53.2 U12.13(PSCK0)
NetR55_1: R55.1 R56.2 U12.14(PSCK1)

Not connected (* = marked no-connect by the designer): U9 3(~{Y}); U10 3(~{Y}); U11 3(~{Y}); U12 1(~{AUDIO}) 2(FSOUT0) 3(FSOUT1) 9(CLKST) 15(COUT) 16(UOUT) 17(EMPH) 18(BFRAME); U13 3(~{Y})

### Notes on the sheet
- FROM XMOS
- SPDIF
- OPTICAL
- IN
- I2S

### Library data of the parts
C56 C66 C67 C70 C73-C76 = CMP-0006237-2: CAP, CERM, 0.1 uF, 16 V, +/- 10%, X7R, AEC-Q200 Grade 1, 0402; Manufacturer: Kemet; TaMin_C: -55°C; Polarized: N; SizeAreaWB_mm2: 3; Value1: Unknown; U/M: EA; Value: 0.1uF; TaMax_C: 125°C; SizeZ_mm: 0.6; SizeX_mm: 1; SizeY_mm: 0.5; Cap_Case: 0402; AEC Qualified: Y; Cap_F: 100nF; AEC Category: Q200
C57 C60-C63 = CMP-0006215-2: CAP, CERM, 10 pF, 50 V, +/- 5%, C0G/NP0, 0402; Manufacturer: Wurth Elektronik; TaMin_C: -55°C; Polarized: N; SizeAreaWB_mm2: 3; Value1: Unknown; U/M: EA; Value: 10pF; TaMax_C: 125°C; SizeZ_mm: 0.6; SizeX_mm: 1; SizeY_mm: 0.5; Cap_Case: 0402; AEC Category: Q200
C58 C59 = CMP-0006887-4: CAP, CERM, 18 pF, 50 V, +/- 5%, C0G/NP0, 0603; Manufacturer: Kemet; TaMin_C: -55°C; Polarized: N; SizeAreaWB_mm2: 4.68; Value1: Unknown; U/M: EA; Value: 18pF; TaMax_C: 125°C; SizeZ_mm: 1; SizeX_mm: 1.6; SizeY_mm: 0.8; Cap_Case: 0603; SizeArea_mm2: 1.28; AEC Category: Q200
C64 C65 = CMP-0007003-5: CAP, CERM, 10 uF, 10 V, +/- 20%, X5R, 0603; PartNumber: C1608X5R1A106M080AC; Manufacturer: TDK; Polarized: N; Value: 10uF; U/M: EA; Cap_F: 10µF; ESR_ohm: 7.8m; Value1: 0.0078 ohm; IRMS_A: 1.85A; TaMin_C: -55°C; TaMax_C: 85°C; Cap_Case: 0603; SizeArea_mm2: 1.28; SizeAreaWB_mm2: 4.68; SizeX_mm: 1.6; SizeY_mm: 0.8; SizeZ_mm: 1; AEC Category: Q200
C68 = CMP-0860557-1: CAP, CERM, 4700 pF, 25 V,+/- 10%, X7R, 0402; Manufacturer: Yageo; Polarized: N; SizeY_mm: 0.5; Cap_Case: 0402; Green_Lifecycle: Active; Value: 4700pF; TaMin_C: -55°C; TaMax_C: 125°C; SizeZ_mm: 0.6; U/M: EA; SizeAreaWB_mm2: 3; Cap_F: 4.7nF; SizeX_mm: 1; AEC Category: Q200; Green_REACh: Passed
C69 = CMP-0006331-2: CAP, CERM, 0.068 uF, 50 V, +/- 10%, X7R, AEC-Q200 Grade 1, 0402; Manufacturer: TDK; TaMin_C: -55°C; ESR_ohm: 0.05606; Polarized: N; SizeAreaWB_mm2: 3; Value1: 0.05606 ohm; U/M: EA; TaMax_C: 125°C; SizeZ_mm: 0.6; SizeX_mm: 1; SizeY_mm: 0.5; Cap_Case: 0402; AEC Qualified: Y; Cap_F: 68nF; IRMS_A: 684.724mA; AEC Category: Q200
C71 C77 = CMP-0006372-2: CAP, CERM, 1 uF, 6.3 V, +/- 20%, X5R, 0402; Manufacturer: MuRata; TaMin_C: -55°C; Polarized: N; SizeAreaWB_mm2: 3; Value1: Unknown; U/M: EA; Value: 1uF; TaMax_C: 85°C; SizeZ_mm: 0.6; SizeX_mm: 1; SizeY_mm: 0.5; Cap_Case: 0402; Cap_F: 1µF; AEC Category: Q200
C72 = CMP-0006308-2: CAP, CERM, 100 pF, 50 V, +/- 5%, C0G/NP0, AEC-Q200 Grade 1, 0402; Manufacturer: TDK; TaMin_C: -55°C; Polarized: N; SizeAreaWB_mm2: 3; Value1: Unknown; U/M: EA; Value: 100pF; TaMax_C: 125°C; SizeZ_mm: 0.6; SizeX_mm: 1; SizeY_mm: 0.5; Cap_Case: 0402; AEC Qualified: Y; AEC Category: Q200
D4 = CMP-0002889-2: as D3 on sheet AMPS116A_USB
J5-J8 = CMP-0002334-1: Header, 100mil, 3x1, Gold, TH; Manufacturer: Sullins Connector Solutions; CNHeader: TRUE; Green_Lifecycle: Not Set; Green_REACh: Incomplete; CT: FALSE
Q1 = CMP-0000326-2: Transistor, PNP, 40 V, 0.2 A, SOT-23; Manufacturer: Diodes Inc.; TaMax_C: 150°C; Value2: 400; Value1: 0.2 A; Vcesat1_V: 250mV; SizeX_mm: 2.5; SizeY_mm: 3; TaMin_C: -55°C; IcRated_A: 200mA; CompType: BJT; SizeZ_mm: 1.1; Value: 40 V; SizeArea_mm2: 7.5; NPN: 0; Vceo_V: 40V; PNP: 1; AEC Category: Q101; SizeAreaWB_mm2: 14; U/M: EA
R37-R42 R44 R45 R49 = CMP-0026404-2: RES, 49.9, 1%, 0.063 W, AEC-Q200 Grade 0, 0402; PartNumber: CRCW040249R9FKED; Manufacturer: Vishay-Dale; Value: 49.9; Value_Code: 49R9; Power_W: 63mW; Value2: 0.063W; VDC_V: 50V; TempCo: 100 ppm/C; EIA_Code: E96; AEC Category: Q200; AEC Grade: 0; AEC Qualified: Y; SizeArea_mm2: 0.5; SizeX_mm: 1; SizeZ_mm: 0.6
R43 = CMP-0023129-5: RES, 470, 1%, 0.1 W, 0603; PartNumber: RC0603FR-07470RL; Manufacturer: Yageo; Value: 470; Value_Code: 470R; Power_W: 100mW; Value2: 0.1W; VDC_V: 75V; TempCo: 100 ppm/C; AEC Category: Q200; AEC Qualified: N; SizeArea_mm2: 1.28; SizeAreaWB_mm2: 4.68; SizeX_mm: 1.6; SizeY_mm: 0.8; SizeZ_mm: 1
R46 R48 R52 R53 R55 = CMP-0026414-2: RES, 4.99 k, 1%, 0.063 W, AEC-Q200 Grade 0, 0402; PartNumber: CRCW04024K99FKED; Manufacturer: Vishay-Dale; Value: 4.99k; Value_Code: 4k99; Power_W: 63mW; Value2: 0.063W; VDC_V: 50V; TempCo: 100 ppm/C; EIA_Code: E96; AEC Category: Q200; AEC Grade: 0; AEC Qualified: Y; SizeArea_mm2: 0.5; SizeX_mm: 1; SizeZ_mm: 0.6
R47 = CMP-0026656-1: RES, 100, 1%, 0.1 W, 0402; PartNumber: ERJ-2RKF1000X; Manufacturer: Panasonic; Value: 100; Value_Code: 100R; Power_W: 100mW; Value2: 0.1W; VDC_V: 50V; TempCo: 100 ppm/C; EIA_Code: E96; U/M: EA; AEC Category: Q200; SizeArea_mm2: 0.5; SizeX_mm: 1; SizeZ_mm: 0.6
R50 = CMP-0026505-2: RES, 681, 1%, 0.063 W, AEC-Q200 Grade 0, 0402; PartNumber: CRCW0402681RFKED; Manufacturer: Vishay-Dale; Value: 681; Value_Code: 681R; Power_W: 63mW; Value2: 0.063W; VDC_V: 50V; TempCo: 100 ppm/C; EIA_Code: E96; AEC Category: Q200; AEC Grade: 0; AEC Qualified: Y; SizeArea_mm2: 0.5; SizeX_mm: 1; SizeZ_mm: 0.6
R51 = CMP-0025950-3: RES, 100 k, 1%, 0.063 W, AEC-Q200 Grade 0, 0402; PartNumber: CRCW0402100KFKED; Manufacturer: Vishay-Dale; Value: 100k; Power_W: 63mW; Value2: 0.063W; VDC_V: 50V; TempCo: 100 ppm/C; EIA_Code: E96; AEC Category: Q200; AEC Grade: 0; AEC Qualified: Y; SizeArea_mm2: 0.5; SizeX_mm: 1; SizeZ_mm: 0.6
R54 = CMP-0025958-3: RES, 10.0 k, 1%, 0.063 W, AEC-Q200 Grade 0, 0402; PartNumber: CRCW040210K0FKED; Manufacturer: Vishay-Dale; Value: 10.0k; Res_ohm: 10k; Value_Code: 10k0; Power_W: 63mW; Value2: 0.063W; VDC_V: 50V; TempCo: 100 ppm/C; EIA_Code: E96; AEC Category: Q200; AEC Grade: 0; AEC Qualified: Y; SizeArea_mm2: 0.5; SizeX_mm: 1; SizeZ_mm: 0.6
R56 = CMP-0026414-2: RES, 4.99 k, 1%, 0.063 W, AEC-Q200 Grade 0, 0402; PartNumber: CRCW04024K99FKED; Manufacturer: Vishay-Dale; CompType: Resistor; Value: 4.99k; Value_Code: 4k99; Power_W: 63mW; Value2: 0.063W; VDC_V: 50V; TempCo: 100 ppm/C; EIA_Code: E96; AEC Category: Q200; AEC Grade: 0; AEC Qualified: Y; SizeArea_mm2: 0.5; SizeX_mm: 1; SizeZ_mm: 0.6
R57 = CMP-0026910-3: RES, 360, 5%, 0.063 W, AEC-Q200 Grade 0, 0402; PartNumber: CRCW0402360RJNED; Manufacturer: Vishay-Dale; Value: 360; Value_Code: 360R; Power_W: 63mW; Value2: 0.063W; VDC_V: 50V; TempCo: 200 ppm/C; EIA_Code: E24; AEC Category: Q200; AEC Grade: 0; AEC Qualified: Y; SizeArea_mm2: 0.5; SizeX_mm: 1; SizeZ_mm: 0.6
S3 = CMP-0002268-2: Switch, SPDT, On-On, 1 Pos, 0.4A, 28 VDC, TH; PartNumber: FT1D-4M-Z; Manufacturer: Copal Electronics; PositionCount: 2; CurrentRating_mA: 400A; VDC_V: 28V
U8 = CMP-0004896-1: Photolink- Fiber Optic Receiver, TH; PartNumber: PLR135/T10; Manufacturer: Everlight
U9-U11 U13 = CMP-0051026-2: Single 2-Line to 1-Line Data Selector/Multiplexer, DCU0008A, LARGE T&R; Alternate PartNumber: SN74LVC2G157DCUT; Manufacturer: Texas Instruments; Generic Part Number: SN74LVC2G157; CompType: IC; 3-State Output: No; AEC Category: Q200; AEC Qualified: N; Bits(#): 2; F @ Nom Voltage(Max)(Mhz): 150; Green_Lifecycle: Active; Green_REACh: Passed; ICC @ Nom Voltage(Max)(mA): 0.01; Input Type: CMOS/TTL; Logic: True; Output Drive (IOL/IOH)(Max)(mA): 32/-32; Output Type: CMOS; Rating: Catalog; SizeArea_mm2: 6.4; SizeAreaWB_mm2: 12.6; SizeX_mm: 3.2; SizeY_mm: 2.0; SizeZ_mm: 0.9; Specialty Logic Family: Decoder/Encoder/Multiplexer; Technology Family: LVC; tpd @ Nom Voltage(Max)(ns): 14,8,6,4; VCC(Max)(V): 5.5; VCC(Min)(V): 1.65; Voltage(Nom)(V): 1.8,2.5,3.3,5
U12 = CMP-0028713-1: Automotive Catalog 96-kHz 24-Bit Digital Audio Interface Receiver, 50 ps Jitter, 3.3V, -40 to 85 degC, 28-Pin TSSOP (PW), Green (RoHS & no Sb/Br); Manufacturer: Texas Instruments; SubFamily: Digital Audio Receiver; Jitter(ps): 50; Sampling Rate(Max)(kHz): 108; Supply Voltage(s)(V): 3.3
U14 = CMP-0073678-3: 5.5V, 4A, 16mΩ Automotive Load Switch With Adjustable Rise Time and Optional Quick Output Discharge, DSG0008B (WSON-8); Alternate PartNumber: TPS22965TDSGTQ1; Manufacturer: Texas Instruments; CompType: IC; U/M: EA; AEC Category: Q200; AEC Qualified: Y; Green_Lifecycle: Active; Green_REACh: Passed; SizeArea_mm2: 4.0; SizeAreaWB_mm2: 9.0; SizeX_mm: 2.0; SizeZ_mm: 0.8
Y1 = CMP-0004595-3: Crystal, 12.288 MHz, 18pF, SMD; PartNumber: ABM8G-12.288MHZ-18-D2Y-T; Manufacturer: Abracon Corporation; TaMin_C: -40°C; TaMax_C: 85°C; Frequency Stability: +/-30ppm

## Sheet AMPS116A_TAS6424-IO.SchDoc: TAS6424MSQ1 I/O
size 431 x 279 mm; Date: Not shown in title block; ApprovedBy: Not shown in title block; CheckedBy: Not shown in title block; Author: Not shown in title block; CompanyName: Not shown in title block; DrawnBy: GJS; Engineer: Not shown in title block; Organization: Not shown in title block; Address1: Not shown in title block; Address2: Not shown in title block; Address3: Not shown in title block; Address4: Not shown in title block; DocumentNumber: 4; Revision: Use project parameter SCH_Rev; SheetNumber: 4; SheetTotal: 6; PageSetup: Record=PageOptions¦CenterHorizontal=True¦CenterVertical=True¦PrintScale=1.00¦XCorrection=1.00¦YCorrection=1.00¦PrintKind=0¦BorderSize=5000000¦LeftOffset=0¦BottomOffset=0¦Orientation=2¦PaperLength=1000¦PaperWidth=1000¦Scale=100¦PaperSource=15¦PrintQuality=600¦MediaType=1¦DitherType=10¦PaperKind=Letter¦PrintScaleMode=1
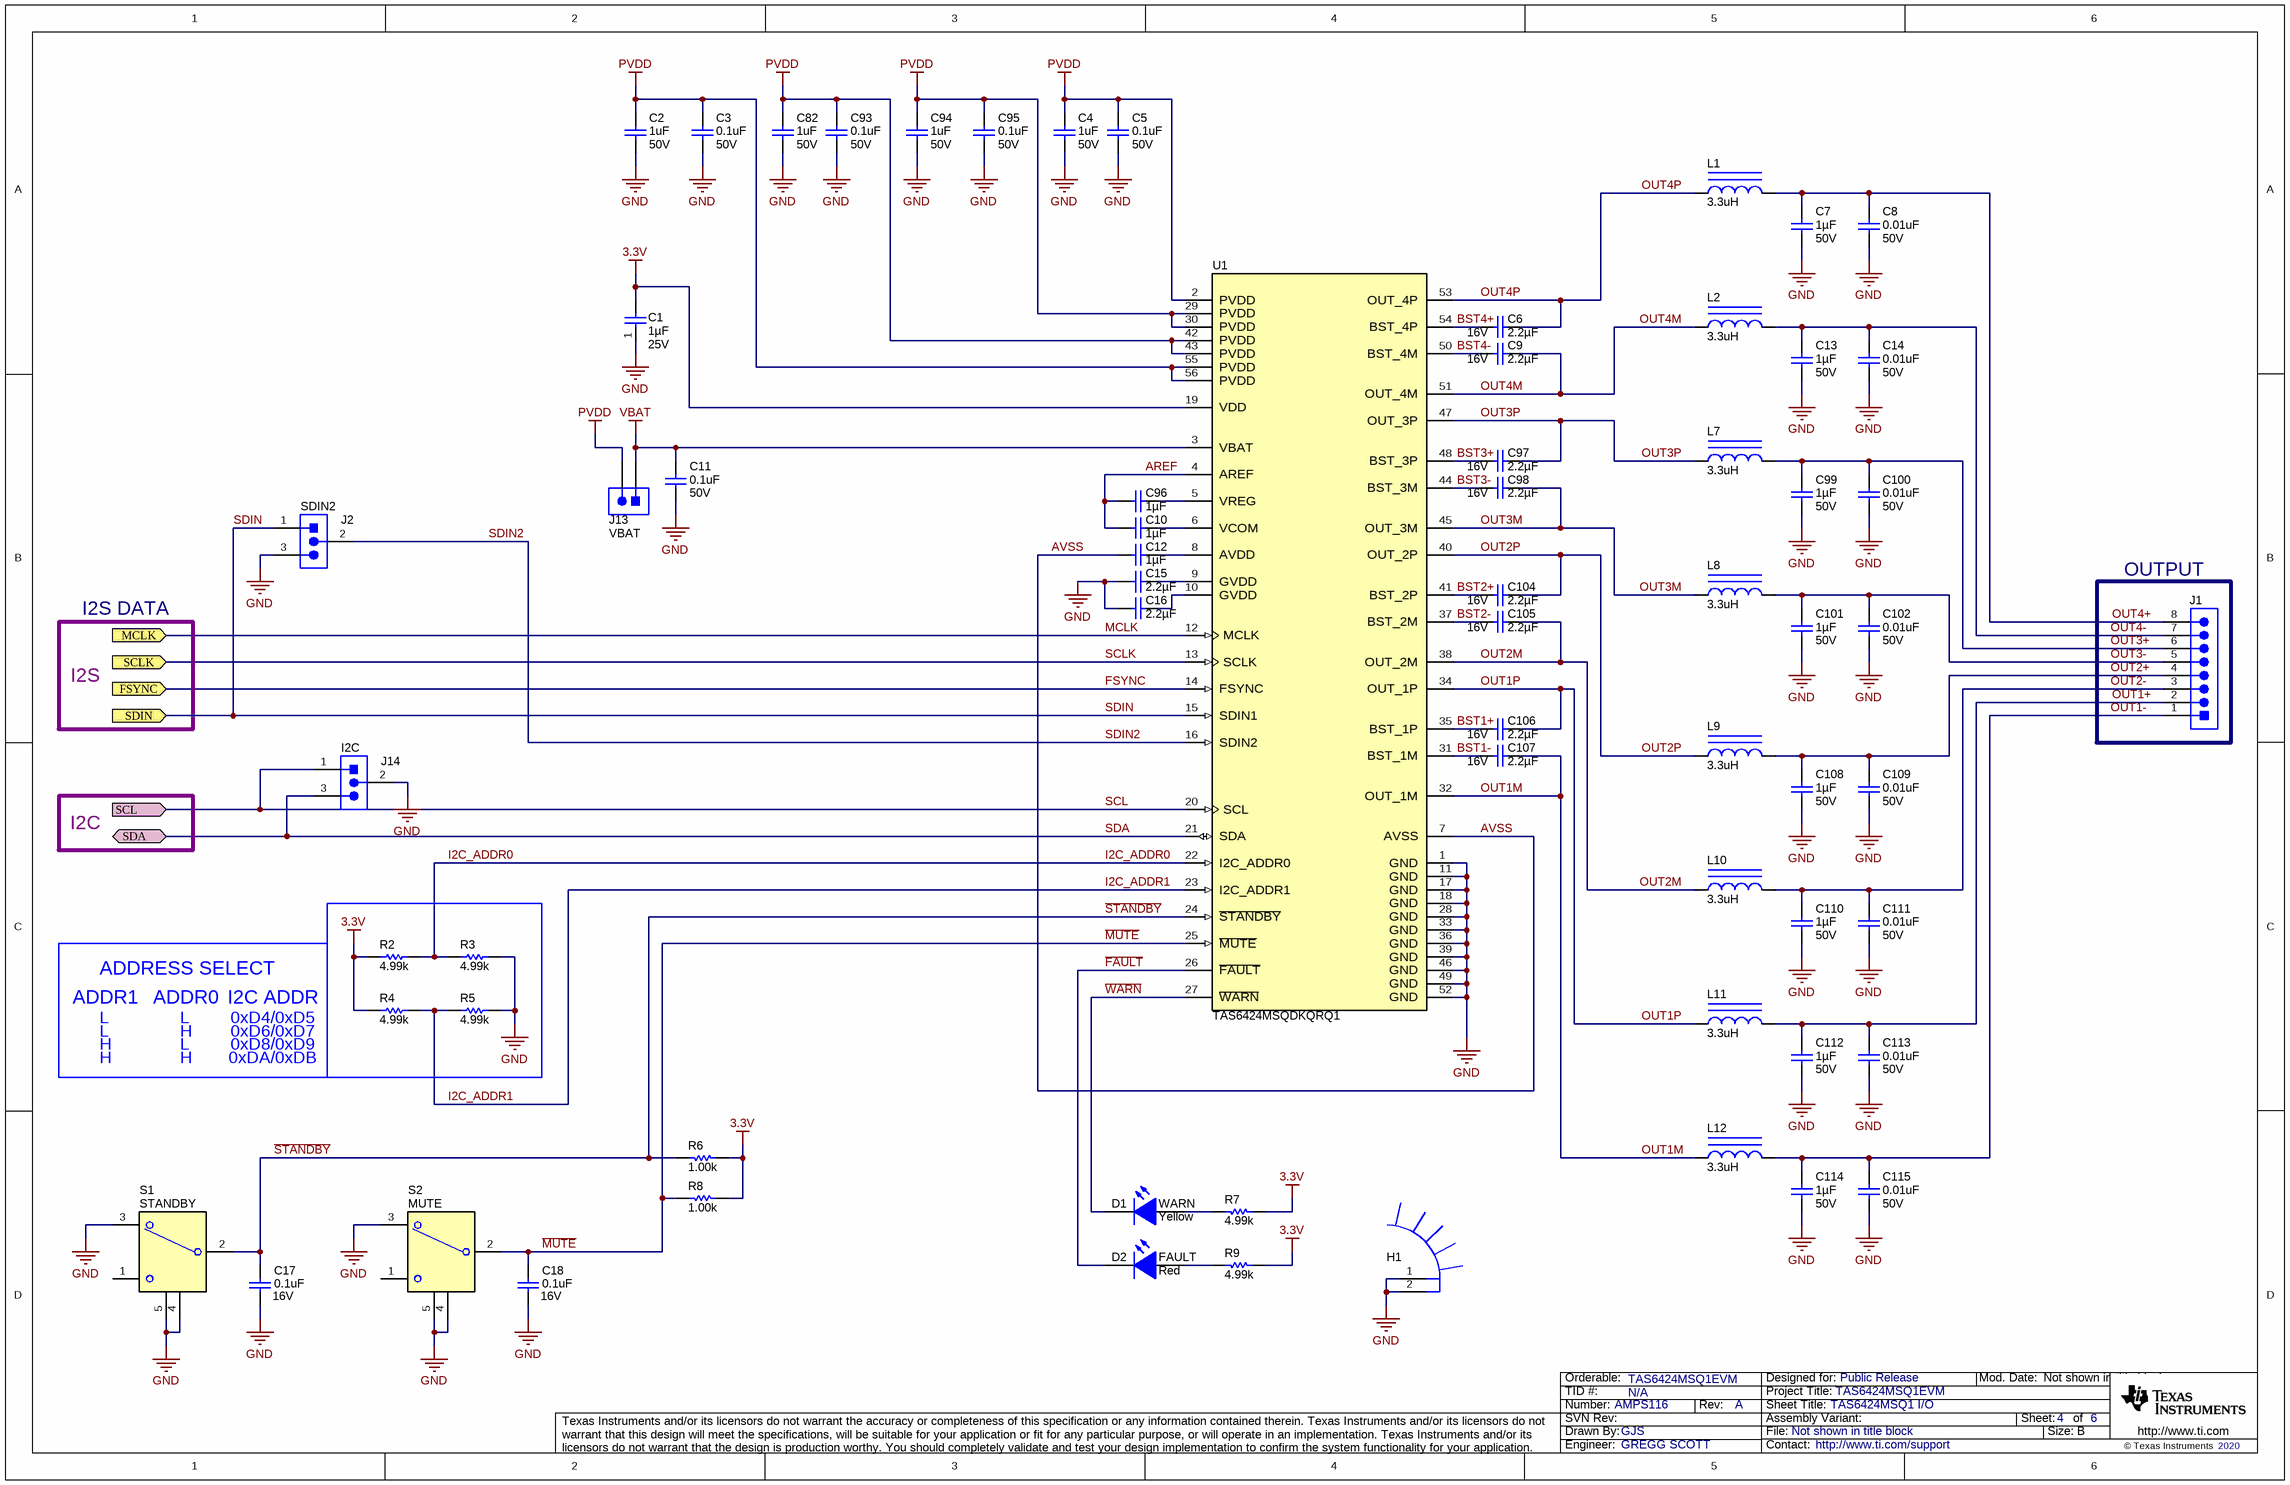
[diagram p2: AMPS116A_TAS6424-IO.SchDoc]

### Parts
C1  Cap_F: 1µF  VDC_V: 25V  [0603L]  (hidden comment: C0603C105K3RACTU)
C2  ValueDisplayed: 1uF  VDC_V: 50V  [0603L]  (hidden comment: Capacitor)
C3  Cap_F: 0.1uF  VDC_V: 50V  [0603L]  (hidden comment: C0603C104K5RACTU)
C4  ValueDisplayed: 1uF  VDC_V: 50V  [0603L]  (hidden comment: Capacitor)
C5  Cap_F: 0.1uF  VDC_V: 50V  [0603L]  (hidden comment: C0603C104K5RACTU)
C6  Cap_F: 2.2µF  VDC_V: 16V  [0603L]  (hidden comment: EMK107BB7225KA-T)
C7  Cap_F: 1µF  VDC_V: 50V  [0805L]  (hidden comment: C0805C105K5RACTU)
C8  ValueDisplayed: 0.01uF  VDC_V: 50V  [0402L]  (hidden comment: Capacitor)
C9  Cap_F: 2.2µF  VDC_V: 16V  [0603L]  (hidden comment: EMK107BB7225KA-T)
C10  Cap_F: 1µF  [0603L]  (hidden comment: C0603C105K3RACTU)
C11  Cap_F: 0.1uF  VDC_V: 50V  [0603L]  (hidden comment: C0603C104K5RACTU)
C12  Cap_F: 1µF  [0603L]  (hidden comment: C0603C105K3RACTU)
C13  Cap_F: 1µF  VDC_V: 50V  [0805L]  (hidden comment: C0805C105K5RACTU)
C14  ValueDisplayed: 0.01uF  VDC_V: 50V  [0402L]  (hidden comment: Capacitor)
C15  Cap_F: 2.2µF  [0603L]  (hidden comment: EMK107BB7225KA-T)
C16  Cap_F: 2.2µF  [0603L]  (hidden comment: EMK107BB7225KA-T)
C17  VDC_V: 16V  ValueDisplayed: 0.1uF  [0402L]  (hidden comment: C0402C104K4RACAUTO)
C18  VDC_V: 16V  ValueDisplayed: 0.1uF  [0402L]  (hidden comment: C0402C104K4RACAUTO)
C82  ValueDisplayed: 1uF  VDC_V: 50V  [0603L]  (hidden comment: Capacitor)
C93  Cap_F: 0.1uF  VDC_V: 50V  [0603L]  (hidden comment: C0603C104K5RACTU)
C94  ValueDisplayed: 1uF  VDC_V: 50V  [0603L]  (hidden comment: Capacitor)
C95  Cap_F: 0.1uF  VDC_V: 50V  [0603L]  (hidden comment: C0603C104K5RACTU)
C96  Cap_F: 1µF  [0603L]  (hidden comment: C0603C105K3RACTU)
C97  Cap_F: 2.2µF  VDC_V: 16V  [0603L]  (hidden comment: EMK107BB7225KA-T)
C98  Cap_F: 2.2µF  VDC_V: 16V  [0603L]  (hidden comment: EMK107BB7225KA-T)
C99  Cap_F: 1µF  VDC_V: 50V  [0805L]  (hidden comment: C0805C105K5RACTU)
C100  ValueDisplayed: 0.01uF  VDC_V: 50V  [0402L]  (hidden comment: Capacitor)
C101  Cap_F: 1µF  VDC_V: 50V  [0805L]  (hidden comment: C0805C105K5RACTU)
C102  ValueDisplayed: 0.01uF  VDC_V: 50V  [0402L]  (hidden comment: Capacitor)
C104  Cap_F: 2.2µF  VDC_V: 16V  [0603L]  (hidden comment: EMK107BB7225KA-T)
C105  Cap_F: 2.2µF  VDC_V: 16V  [0603L]  (hidden comment: EMK107BB7225KA-T)
C106  Cap_F: 2.2µF  VDC_V: 16V  [0603L]  (hidden comment: EMK107BB7225KA-T)
C107  Cap_F: 2.2µF  VDC_V: 16V  [0603L]  (hidden comment: EMK107BB7225KA-T)
C108  Cap_F: 1µF  VDC_V: 50V  [0805L]  (hidden comment: C0805C105K5RACTU)
C109  ValueDisplayed: 0.01uF  VDC_V: 50V  [0402L]  (hidden comment: Capacitor)
C110  Cap_F: 1µF  VDC_V: 50V  [0805L]  (hidden comment: C0805C105K5RACTU)
C111  ValueDisplayed: 0.01uF  VDC_V: 50V  [0402L]  (hidden comment: Capacitor)
C112  Cap_F: 1µF  VDC_V: 50V  [0805L]  (hidden comment: C0805C105K5RACTU)
C113  ValueDisplayed: 0.01uF  VDC_V: 50V  [0402L]  (hidden comment: Capacitor)
C114  Cap_F: 1µF  VDC_V: 50V  [0805L]  (hidden comment: C0805C105K5RACTU)
C115  ValueDisplayed: 0.01uF  VDC_V: 50V  [0402L]  (hidden comment: Capacitor)
D1  WARN  value Yellow  [LED_LTST-C170]
D2  FAULT  value Red  [LED_LTST-C170_Red]
H1  HeatSink_2  [HEATSINK-DKQ56_20MMX41_4X32_77MM]  (value not drawn)
J1  OUTPUT  [On-Shore_ED555_8DS]  (value not drawn)
J2  SDIN2  [PBC03SAAN]
J13  VBAT  [Sullins_PBC02SAAN]
J14  I2C  [PBC03SAAN]
L1  ValueDisplayed: 3.3uH  [VCMT053T]  (hidden comment: VCMT053T-3R3MN5)
L2  ValueDisplayed: 3.3uH  [VCMT053T]  (hidden comment: VCMT053T-3R3MN5)
L7  ValueDisplayed: 3.3uH  [VCMT053T]  (hidden comment: VCMT053T-3R3MN5)
L8  ValueDisplayed: 3.3uH  [VCMT053T]  (hidden comment: VCMT053T-3R3MN5)
L9  ValueDisplayed: 3.3uH  [VCMT053T]  (hidden comment: VCMT053T-3R3MN5)
L10  ValueDisplayed: 3.3uH  [VCMT053T]  (hidden comment: VCMT053T-3R3MN5)
L11  ValueDisplayed: 3.3uH  [VCMT053T]  (hidden comment: VCMT053T-3R3MN5)
L12  ValueDisplayed: 3.3uH  [VCMT053T]  (hidden comment: VCMT053T-3R3MN5)
R2  ValueDisplayed: 4.99k  [0402L]  (hidden comment: DNP)
R3  ValueDisplayed: 4.99k  [0402L]
R4  ValueDisplayed: 4.99k  [0402L]  (hidden comment: DNP)
R5  ValueDisplayed: 4.99k  [0402L]
R6  ValueDisplayed: 1.00k  [0402L]  (hidden comment: Resistor)
R7  ValueDisplayed: 4.99k  [0402L]  (hidden comment: Resistor)
R8  ValueDisplayed: 1.00k  [0402L]
R9  ValueDisplayed: 4.99k  [0402L]  (hidden comment: Resistor)
S1  STANDBY  [SW_FT1D-4M-Z]
S2  MUTE  [SW_FT1D-4M-Z]
U1  TAS6424MSQDKQRQ1  [DKQ0056A-MFG]

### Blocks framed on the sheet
OUTPUT: J1

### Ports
FSYNC (in), MCLK (in), SCL (in), SCLK (in), SDA (bidir), SDIN (in)

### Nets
3.3V: C1.2 R2.2 R4.2 R6.1 R7.2 R8.1 R9.2 U1.19(VDD)
GND: C1.1 C2.2 C3.1 C4.2 C5.1 C7.2 C8.1 C11.1 C13.2 C14.1 C15.1 C16.1 C17.2 C18.2 C82.1 C93.1 C94.2 C95.1 C99.2 C100.1 C101.2 C102.1 C108.2 C109.1 C110.2 C111.1 C112.2 C113.1 C114.2 C115.1 H1.1 H1.2 J2.3 J14.2 R3.1 R5.1 S1.3 S1.4 S1.5 S2.3 S2.4 S2.5 U1.1(GND) U1.11(GND) U1.17(GND) U1.18(GND) U1.28(GND) U1.33(GND) U1.36(GND) U1.39(GND) U1.46(GND) U1.49(GND) U1.52(GND)
PVDD: C2.1 C3.2 C4.1 C5.2 C82.2 C93.2 C94.1 C95.2 J13.2 U1.2(PVDD) U1.29(PVDD) U1.30(PVDD) U1.42(PVDD) U1.43(PVDD) U1.55(PVDD) U1.56(PVDD)
VBAT: C11.2 J13.1 U1.3(VBAT)
~{FAULT}: D2.2(K) U1.26(~{FAULT})
~{MUTE}: C18.1 R8.2 S2.2(COM) U1.25(~{MUTE})
~{STANDBY}: C17.1 R6.2 S1.2(COM) U1.24(~{STANDBY})
~{WARN}: D1.2(K) U1.27(~{WARN})
AREF: C10.1 C96.1 U1.4(AREF)
AVSS: C12.1 U1.7(AVSS)
BST1+: C106.1 U1.35(BST_1P)
BST1-: C107.1 U1.31(BST_1M)
BST2+: C104.1 U1.41(BST_2P)
BST2-: C105.1 U1.37(BST_2M)
BST3+: C97.1 U1.48(BST_3P)
BST3-: C98.1 U1.44(BST_3M)
BST4+: C6.1 U1.54(BST_4P)
BST4-: C9.1 U1.50(BST_4M)
FSYNC: U1.14(FSYNC) ; port FSYNC
I2C_ADDR0: R2.1 R3.2 U1.22(I2C_ADDR0)
I2C_ADDR1: R4.1 R5.2 U1.23(I2C_ADDR1)
MCLK: U1.12(MCLK) ; port MCLK
OUT1+: C112.1 C113.2 J1.2 L11.2
OUT1-: C114.1 C115.2 J1.1 L12.2
OUT1M: C107.2 L12.1 U1.32(OUT_1M)
OUT1P: C106.2 L11.1 U1.34(OUT_1P)
OUT2+: C108.1 C109.2 J1.4 L9.2
OUT2-: C110.1 C111.2 J1.3 L10.2
OUT2M: C105.2 L10.1 U1.38(OUT_2M)
OUT2P: C104.2 L9.1 U1.40(OUT_2P)
OUT3+: C99.1 C100.2 J1.6 L7.2
OUT3-: C101.1 C102.2 J1.5 L8.2
OUT3M: C98.2 L8.1 U1.45(OUT_3M)
OUT3P: C97.2 L7.1 U1.47(OUT_3P)
OUT4+: C7.1 C8.2 J1.8 L1.2
OUT4-: C13.1 C14.2 J1.7 L2.2
OUT4M: C9.2 L2.1 U1.51(OUT_4M)
OUT4P: C6.2 L1.1 U1.53(OUT_4P)
SCL: J14.1 U1.20(SCL) ; port SCL
SCLK: U1.13(SCLK) ; port SCLK
SDA: J14.3 U1.21(SDA) ; port SDA
SDIN: J2.1 U1.15(SDIN1) ; port SDIN
SDIN2: J2.2 U1.16(SDIN2)
NetC10_2: C10.2 U1.6(VCOM)
NetC12_2: C12.2 U1.8(AVDD)
NetC15_2: C15.2 U1.9(GVDD)
NetC16_2: C16.2 U1.10(GVDD)
NetC96_2: C96.2 U1.5(VREG)
NetD1_1: D1.1(A) R7.1
NetD2_1: D2.1(A) R9.1

Not connected (* = marked no-connect by the designer): S1 1; S2 1

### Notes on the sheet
- I2S DATA
- I2S
- I2C
- ADDR1
- ADDRESS SELECT
- L
- ADDR0
- H
- I2C ADDR
- 0xD4/0xD5
- 0xD6/0xD7
- 0xD8/0xD9
- 0xDA/0xDB

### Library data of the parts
C1 = CMP-0006867-4: CAP, CERM, 1 uF, 25 V, +/- 10%, X7R, 0603; Manufacturer: Kemet; TaMin_C: -55°C; Polarized: N; SizeAreaWB_mm2: 4.68; Value1: Unknown; U/M: EA; Value: 1uF; TaMax_C: 125°C; SizeZ_mm: 1; SizeX_mm: 1.6; SizeY_mm: 0.8; Cap_Case: 0603; SizeArea_mm2: 1.28; AEC Category: Q200
C2 C4 C82 C94 = CMP-0007508-5: CAP, CERM, 1 uF, 50 V, +/- 10%, X7R, 0603; PartNumber: UMK107AB7105KA-T; Manufacturer: Taiyo Yuden; Polarized: N; Value: 1uF; U/M: EA; Cap_F: 1µF; Value1: Unknown; TaMin_C: -55°C; TaMax_C: 125°C; Cap_Case: 0603; AEC Category: Q200; SizeArea_mm2: 1.28; SizeAreaWB_mm2: 4.68; SizeX_mm: 1.6; SizeY_mm: 0.8; SizeZ_mm: 1
C3 C5 C11 C93 C95 = CMP-0006861-4: CAP, CERM, 0.1 uF, 50 V, +/- 10%, X7R, 0603; Manufacturer: Kemet; TaMin_C: -55°C; Polarized: N; SizeAreaWB_mm2: 4.68; Value1: Unknown; U/M: EA; Value: 0.1uF; TaMax_C: 125°C; SizeZ_mm: 1; SizeX_mm: 1.6; SizeY_mm: 0.8; Cap_Case: 0603; SizeArea_mm2: 1.28; AEC Category: Q200
C6 C9 C97 C98 C104-C107 = CMP-0007121-4: CAP, CERM, 2.2 uF, 16 V, +/- 10%, X7R, 0603; Manufacturer: Taiyo Yuden; TaMin_C: -55°C; Polarized: N; SizeAreaWB_mm2: 4.68; Value1: Unknown; U/M: EA; Value: 2.2uF; TaMax_C: 125°C; SizeZ_mm: 1; SizeX_mm: 1.6; SizeY_mm: 0.8; Cap_Case: 0603; SizeArea_mm2: 1.28; AEC Category: Q200
C7 C13 C99 C101 C108 C110 C112 C114 = CMP-0007730-2: CAP, CERM, 1 uF, 50 V, +/- 10%, X7R, 0805; Manufacturer: Kemet; TaMin_C: -55°C; Polarized: N; SizeAreaWB_mm2: 6.75; Value1: Unknown; U/M: EA; Value: 1uF; TaMax_C: 125°C; SizeZ_mm: 1.45; SizeX_mm: 2; SizeY_mm: 1.25; Cap_Case: 0805; SizeArea_mm2: 2.5; AEC Category: Q200
C8 C14 C100 C102 C109 C111 C113 C115 = CMP-0006355-2: CAP, CERM, 0.01 uF, 50 V, +/- 10%, C0G/NP0, 0402; PartNumber: GCM155R71H103KA55D; Manufacturer: MuRata; Polarized: N; Value: 0.01uF; U/M: EA; Cap_F: 10nF; Value1: Unknown; TaMin_C: -55°C; TaMax_C: 125°C; Cap_Case: 0402; AEC Category: Q200; SizeArea_mm2: 0.5; SizeAreaWB_mm2: 3; SizeX_mm: 1; SizeZ_mm: 0.6
C10 C12 C96 = CMP-0006867-4: CAP, CERM, 1 uF, 25 V, +/- 10%, X7R, 0603; Manufacturer: Kemet; TaMin_C: -55°C; Polarized: N; SizeAreaWB_mm2: 4.68; Value1: Unknown; U/M: EA; Value: 1uF; TaMax_C: 125°C; SizeZ_mm: 1; SizeX_mm: 1.6; SizeY_mm: 0.8; Cap_Case: 0603; Value2: 25V; SizeArea_mm2: 1.28; AEC Category: Q200
C15 C16 = CMP-0007121-4: CAP, CERM, 2.2 uF, 16 V, +/- 10%, X7R, 0603; Manufacturer: Taiyo Yuden; TaMin_C: -55°C; Polarized: N; SizeAreaWB_mm2: 4.68; Value1: Unknown; U/M: EA; Value: 2.2uF; TaMax_C: 125°C; SizeZ_mm: 1; SizeX_mm: 1.6; SizeY_mm: 0.8; Cap_Case: 0603; Value2: 16V; SizeArea_mm2: 1.28; AEC Category: Q200
C17 C18 = CMP-0006237-2: as C56 on sheet AMPS116A_SPDIF
D1 = CMP-0002862-2: LED, Yellow , SMD; PartNumber: LTST-C170KSKT; Manufacturer: Lite-On; SizeY_mm: 1.25; SizeZ_mm: 1.2; SizeX_mm: 2; Vf_V: 2V; Type: AlInGaP; SizeAreaWB_mm2: 6.75; Value1: W; Io_A: 20mA; SizeArea_mm2: 2.5
D2 = CMP-0002829-3: LED, Red, SMD; Manufacturer: Lite-On; PartNumber: LTST-C170KRKT; SizeZ_mm: 1.2; Value1: W; SizeY_mm: 1.25; Value2: 2V; SizeArea_mm2: 2.5; SizeX_mm: 2; SizeAreaWB_mm2: 6.75; Io_A: 20mA; Type: AlInGaP
H1 = CMP-0004050-1: Heat Sink for DKQ Packages, 41.4x20 mm; Manufacturer: Any; PartNumber: HS-DKQ56_20X41.4X32.77
J1 = CMP-0075135-1: Terminal Block, 3.5mm, 8-Pos, TH; Manufacturer: On-Shore Technology; PartNumber: ED555/8DS; CNHeader: False; Green_Lifecycle: Not Set; Shrouded: Y; Gender: Male; Green_REACh: Incomplete; Row_Count: 1; Pitch_mm: 3.5; ContactFinish: Brass; CT: True
J2 J14 = CMP-0002334-1: as J5 on sheet AMPS116A_SPDIF
J13 = CMP-0054566-1: Header, 100mil, 2x1, Gold, TH; PartNumber: PBC02SAAN; Manufacturer: Sullins Connector Solutions; Cert_UL: Y; CNHeader: TRUE; CT: FALSE; Current_A: 3A; Gender: Male; Green_Lifecycle: Active; Green_REACh: Passed; Pitch_mm: 2.54; Row_Count: 1; Shrouded: N; Voltage_V: 1.8kV
L1 L2 L7-L12 = CMP-0059924-1: Inductor, 3.3 uH, 4.5 A, 0.038 ohm, AEC-Q200 Grade 0, SMD; Manufacturer: Cyntec; Isat: 4.5A @ 30% inductance drop; Irms: 5A @ 40C rise; SizeAreaWB_mm2: 54.0125; DCR_ohm: 0.038; Value: 3.3uH; Imax_A: 4.5A; SizeZ_mm: 3; SizeX_mm: 5.45; SizeY_mm: 5.25; SizeArea_mm2: 28.6125; Ind_H: 3.3µH; AEC Qualified: Y; AEC Grade: 0; AEC Category: Q200
R2-R5 = CMP-0026414-2: as R56 on sheet AMPS116A_SPDIF
R6 R8 = CMP-0026071-3: RES, 1.00 k, 1%, 0.063 W, AEC-Q200 Grade 0, 0402; PartNumber: CRCW04021K00FKED; Manufacturer: Vishay-Dale; Value: 1.00k; Res_ohm: 1k; Value_Code: 1k00; Power_W: 63mW; Value2: 0.063W; VDC_V: 50V; TempCo: 100 ppm/C; EIA_Code: E96; AEC Category: Q200; AEC Qualified: Y; AEC Grade: 0; SizeArea_mm2: 0.5; SizeX_mm: 1; SizeZ_mm: 0.6
R7 R9 = CMP-0026414-2: as R46 on sheet AMPS116A_SPDIF
S1 S2 = CMP-0002268-2: as S3 on sheet AMPS116A_SPDIF
U1 = CMP-0089860-1: 45-W, 2-MHz Digital Input 4-Channel Automotive Class-D Audio Amplifier with Load Dump Protection and I 2C Diagnostics; Manufacturer: Texas Instruments; TJmax_C: +150°C; Standoff Height: 0mm; Power At Speaker R: 45W @ 4Ω; Number Of Channels: 4; AEC Grade: Grade 1; Min Supply Voltage: 3V; TaMin_C: -40°C; Bandwidth: 40kHz; SizeZ_mm: 2.475mm; Output Current Per Channel: 6.5A; TaMax_C: +125°C; Max Supply Voltage: 18V; AEC Qualified: Yes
